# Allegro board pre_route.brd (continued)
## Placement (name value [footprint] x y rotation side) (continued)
CN2  0.1uf  [8_PINS_SURFACE_MOUNT]  -155.7 262.49 0 top
CN3  0.1uf  [8_PINS_SURFACE_MOUNT]  -155.7 266.78 0 top
CN4  0.1uf  [8_PINS_SURFACE_MOUNT]  -155.7 271.07 0 top
CN5  0.1uf  [8_PINS_SURFACE_MOUNT]  -155.7 275.36 0 top
CN6  0.1uf  [8_PINS_SURFACE_MOUNT]  -155.7 279.65 0 top
CN7  0.1uf  [8_PINS_SURFACE_MOUNT]  -155.7 236.76 0 top
CN8  0.1uf  [8_PINS_SURFACE_MOUNT]  -155.7 283.94 0 top
CN9  0.1uf  [8_PINS_SURFACE_MOUNT]  -155.7 232.47 0 top
CN10  0.1uf  [8_PINS_SURFACE_MOUNT]  -155.7 245.33 0 top
CN11  0.1uf  [8_PINS_SURFACE_MOUNT]  -155.7 249.62 0 top
CN12  0.1uf  [8_PINS_SURFACE_MOUNT]  -155.7 253.91 0 top
CN13  0.1uf  [8_PINS_SURFACE_MOUNT]  -155.7 258.2 0 top
CON3  VAL  [CFCONN50P]  -25.15 297.56 0 top
HS1  XXX  [HEATSINK-7106D]  162.5 257.94 0 bottom
HS2  XXX  [HEATSINK-7106D]  249.87 36.45 0 bottom
ISO1  XXX  [DIP8]  22.23 202.56 0 top
J1  XXX  [CON120_HM-ZD]  175.26 303.27 180 top
J2  XXX  [VERT_SM_SMA]  237.49 295.91 0 top
J3  XXX  [VERT_SM_SMA]  250.19 295.91 0 top
J4  XXX  [VERT_SM_SMA]  262.89 295.91 0 top
J5  XXX  [VERT_SM_SMA]  275.59 295.91 0 top
J6  XXX  [VERT_SM_SMA]  288.29 295.91 0 top
J11  XXX  [HSSDC2]  326.06 281.3 0 top
J15  XXX  [HSSDC2]  326.06 264.16 0 top
J16  XXX  [VERT_SM_SMA]  219.71 257.81 0 top
J17  XXX  [VERT_SM_SMA]  250.19 255.27 0 top
J18  XXX  [VERT_SM_SMA]  262.89 255.27 0 top
J19  XXX  [VERT_SM_SMA]  275.59 255.27 0 top
J20  XXX  [VERT_SM_SMA]  288.29 255.27 0 top
J23  XXX  [HSSDC2]  326.06 247.01 0 top
J24  XXX  [VERT_SM_SMA]  219.71 245.11 0 top
J25  XXX  [VERT_SM_SMA]  250.19 242.57 0 top
J26  XXX  [VERT_SM_SMA]  262.89 242.57 0 top
J27  XXX  [VERT_SM_SMA]  275.59 242.57 0 top
J28  XXX  [VERT_SM_SMA]  288.29 242.57 0 top
J29  XXX  [VERT_SM_SMA]  154.94 236.22 270 top
J30  XXX  [VERT_SM_SMA]  167.64 236.22 0 top
J31  XXX  [MOLEX-10X2]  28.83 249.43 90 top
J32  XXX  [HSSDC2]  326.06 229.87 0 top
J34  XXX  [MICTOR]  279.4 226.06 0 top
J36  VAL  [HDR2X4_100MIL]  230.25 276.23 270 top
J37  XXX  [VERT_SM_SMA]  152.4 191.77 270 top
J38  XXX  [SFP]  298.98 204.26 90 top
J42  XXX  [TEK_PROBE]  210.19 196.85 90 top
J43  XXX  [VERT_SM_SMA]  152.4 179.07 0 top
J45  XXX  [SFP]  298.98 183.94 90 top
J46  XXX  [VERT_SM_SMA]  110.49 176.53 90 top
J47  XXX  [VERT_SM_SMA]  124.46 176.53 90 top
J48  XXX  [TH-CONN-2-P1]  19.69 186.69 270 top
J49  XXX  [VERT_SM_SMA]  165.1 182.88 270 top
J52  XXX  [VERT_SM_SMA]  252.73 173.35 90 top
J53  XXX  [TSM-110-01-G-DV]  266.7 170.18 0 top
J54  XXX  [SFP]  298.98 163.62 90 top
J55  XXX  [TH-CONN-2-P1]  132.72 165.1 0 top
J56  XXX  [TH-CONN-2-P1]  150.5 165.1 180 top
J57  XXX  [SMT_A_PROBE]  225.42 161.93 270 top
J58  XXX  [SMT_A_PROBE]  236.85 161.93 270 top
J59  XXX  [TEK_PROBE]  210.19 161.92 90 top
J60  XXX  [VERT_SM_SMA]  252.73 160.66 90 top
J61  XXX  [VERT_SM_SMA]  127.63 158.11 90 top
J62  XXX  [VERT_SM_SMA]  142.24 158.11 90 top
J63  XXX  [TSM-105-01-L-DV]  266.7 147.32 0 top
J64  XXX  [SFP]  298.98 143.3 90 top
J68  XXX  [TSM-110-01-G-DV]  170.81 146.05 180 top
J69  XXX  [VERT_SM_SMA]  210.82 138.43 0 top
J72  XXX  [EDGE_LAUNCHED_SMA]  329.39 128.31 0 top
J75  XXX  [MICTOR]  102.23 146.05 180 top
J76  XXX  [VERT_SM_SMA]  207.64 117.47 0 top
J77  XXX  [EDGE_LAUNCHED_SMA]  329.39 113.07 0 top
J78  XXX  [HDR2X10_100MIL]  39.37 106.68 270 top
J79  XXX  [HDR2X7_100MIL]  68.58 106.68 270 top
J80  XXX  [VERT_SM_SMA]  196.22 102.87 270 top
J81  XXX  [EDGE_LAUNCHED_SMA]  329.39 97.83 0 top
J83  XXX  [VERT_SM_SMA]  279.4 93.98 0 top
J84  XXX  [VERT_SM_SMA]  299.72 93.98 0 top
J85  XXX  [TSM-105-01-L-DV]  96.52 91.44 270 top
J86  XXX  [EDGE_LAUNCHED_SMA]  329.39 82.59 0 top
J87  XXX  [10_PIN_CONNECTOR]  96.52 80.64 270 top
J88  XXX  [VERT_SM_SMA]  279.4 78.74 0 top
J89  XXX  [VERT_SM_SMA]  299.72 78.74 0 top
J90  XXX  [TH-CONN-2-P1]  132.08 75.56 90 top
J91  XXX  [VERT_SM_SMA]  177.8 74.93 270 top
J92  XXX  [HDR2X20_100MIL]  52.07 73.66 270 top
J93  XXX  [EDGE_LAUNCHED_SMA]  329.39 67.32 0 top
J94  XXX  [VERT_SM_SMA]  279.4 63.5 0 top
J95  XXX  [VERT_SM_SMA]  299.72 63.5 0 top
J97  XXX  [VERT_SM_SMA]  196.85 54.61 90 top
J98  XXX  [EDGE_LAUNCHED_SMA]  329.39 52.08 0 top
J99  XXX  [VERT_SM_SMA]  279.4 48.26 0 top
J100  XXX  [VERT_SM_SMA]  299.72 48.26 0 top
J101  XXX  [EDGE_LAUNCHED_SMA]  329.39 36.73 0 top
J102  XXX  [VERT_SM_SMA]  279.4 33.02 0 top
J103  XXX  [VERT_SM_SMA]  299.72 33.02 0 top
J104  XXX  [VERT_SM_SMA]  177.8 31.75 90 top
J105  XXX  [EDGE_LAUNCHED_SMA]  329.39 21.49 0 top
J106  XXX  [VERT_SM_SMA]  279.4 17.78 0 top
J107  XXX  [VERT_SM_SMA]  299.72 17.78 0 top
J108  XXX  [CON120_HM-ZD]  167.46 1.91 0 top
J109  XXX  [CON120_HM-ZD]  204.47 1.91 0 top
J111  XXX  [TH-CONN-2-P1]  28.32 257.68 180 top
J112  XXX  [TH-CONN-2-P1]  154.43 267.08 0 top
J113  XXX  [TH-CONN-2-P1]  156.21 204.72 270 top
J114  XXX  [TH-CONN-2-P1]  136.14 278.38 0 top
J121  XXX  [VERT_SM_SMA]  313.69 295.91 0 top
J122  XXX  [VERT_SM_SMA]  300.99 295.91 0 top
J123  VAL  [HDR2X2_100MIL]  230.25 285.75 270 top
J124  XXX  [DB9DOUBLE]  16.51 49.53 90 top
NOREF  -  []  165.73 167.64 0 top
NOREF#2  -  []  75.34 280.47 0 top
NOREF#3  -  []  5.84 280.47 0 top
NOREF#4  -  [unnamed#2]  162.56 161.29 0 top
NOREF#5  -  [unnamed#2]  165.73 173.99 0 top
NOREF#6  -  []  323.85 6.35 0 top
NOREF#7  -  []  6.35 298.45 0 top
NOREF#8  -  [unnamed#2]  326.39 292.1 0 top
NOREF#9  -  [unnamed#2]  111.76 110.49 0 top
NOREF#10  -  []  6.35 6.35 0 top
NOREF#11  -  [unnamed#2]  229.23 301.62 0 top
NOREF#12  -  [unnamed#2]  25.4 7.62 0 top
NOREF#13  -  [unnamed#2]  210.82 17.78 0 top
NOREF#14  -  []  165.73 167.64 0 top
NOREF#15  -  [unnamed#2]  63.5 116.84 0 top
NOREF#16  -  [unnamed#2]  313.69 13.97 0 top
NOREF#17  -  [unnamed#2]  219.71 226.06 0 top
NOREF#18  -  []  -39.38 -132.66 0 top
NOREF#19  -  []  0.63 304.8 0 top
NOREF#20  -  []  -316.23 56.52 0 top
NOREF#21  -  [unnamed#2]  6.35 289.56 0 top
NOREF#22  -  []  323.85 6.35 0 top
NOREF#23  -  [unnamed#2]  222.25 127 0 top
NOREF#24  -  [unnamed#2]  275.59 199.39 0 top
NOREF#25  -  [unnamed#2]  101.6 10.79 0 top
NOREF#26  -  []  6.35 6.35 0 top
NOREF#27  -  [unnamed#2]  245.11 6.22 0 top
NOREF#28  -  []  330.2 0 0 top
NOREF#29  -  []  0 0 0 top
NOREF#30  -  [unnamed#2]  210.82 17.78 180 bottom
NOREF#31  -  [unnamed#2]  63.5 116.84 180 bottom
NOREF#32  -  [unnamed#2]  25.4 7.62 180 bottom
NOREF#33  -  [unnamed#2]  245.11 6.22 180 bottom
NOREF#34  -  [unnamed#2]  165.73 173.99 180 bottom
NOREF#35  -  [unnamed#2]  326.39 292.1 180 bottom
NOREF#36  -  [unnamed#2]  229.23 301.62 180 bottom
NOREF#37  -  [unnamed#2]  313.69 13.97 180 bottom
NOREF#38  -  [unnamed#2]  101.6 10.79 180 bottom
NOREF#39  -  [unnamed#2]  6.35 289.56 180 bottom
PMCJN1  XXX  [SMT]  22.09 164.46 0 bottom
PMCJN2  XXX  [SMT]  22.09 150.46 0 bottom
R1  56  [RES_0402]  -111.7 60.39 0 top
R2  0.056  [THRU_HOLE]  -141.15 49.7 0 top
R3  100  [RES_0402]  -137.2 32.51 0 top
R4  104  [RES_0603]  -144.92 150.21 0 top
R5  20  [RES_0603]  -144.92 146.55 0 top
R6  100  [RES_0402]  -137.2 16.51 0 top
R7  56  [RES_0603]  -111.67 96.71 0 top
R11  56  [RES_0603]  -111.67 136.92 0 top
R15  104  [RES_0402]  -139.05 274.73 0 top
R16  78.7  [RES_0402]  -139.05 256.44 0 top
R17  6.65K  [RES_0402]  -139.05 129.85 0 top
R18  100  [RES_0402]  -137.2 55.37 0 top
R19  4.42K  [RES_0402]  -139.05 70.45 0 top
R21  0  [RES_0402]  -139.05 43.58 0 top
R23  56  [RES_0603]  -111.67 107.68 0 top
R27  162  [RES_0402]  -144.74 263.32 0 top
R28  1.0K  [RES_0402]  -139.05 27.12 0 top
R30  56  [RES_0603]  -111.67 104.02 0 top
R31  1.0K  [RES_0402]  -139.05 24.84 0 top
R32  1.0K  [RES_0402]  -139.05 22.55 0 top
R33  100  [RES_0402]  -137.2 30.22 0 top
R34  2.7K  [RES_0402]  -144.74 171.91 0 top
R35  162  [RES_0402]  -144.74 261.03 0 top
R37  10.0K  [RES_0603]  -137.38 160.27 0 top
R39  1.0K  [RES_0603]  -137.38 284.57 0 top
R40  162  [RES_0402]  -144.74 258.74 0 top
R41  1.0K  [RES_0603]  -137.38 280.91 0 top
R42  10.0K  [RES_0603]  -137.38 156.61 0 top
R43  100  [RES_0402]  -137.2 18.79 0 top
R44  1.0K  [RES_0603]  -137.38 277.25 0 top
R46  162  [RES_0402]  -144.74 256.46 0 top
R47  162  [RES_0402]  -144.74 254.17 0 top
R48  162  [RES_0402]  -144.74 251.89 0 top
R51  10.0K  [RES_0603]  -137.38 152.96 0 top
R52  22  [RES_0402]  -137.2 129.87 0 top
R53  1.0K  [RES_0603]  -137.38 273.6 0 top
R55  10.0K  [RES_0603]  -137.38 149.3 0 top
R56  1.0K  [RES_0603]  -137.38 269.94 0 top
R57  1.0K  [RES_0603]  -137.38 266.29 0 top
R60  100  [RES_0402]  -137.2 14.22 0 top
R61  100  [RES_0402]  -137.2 11.94 0 top
R62  4.7  [RES_0603]  -139.23 60.16 0 top
R65  2.5K  [RES_0603]  -144.92 69.78 0 top
R66  2.5K  [RES_0603]  -144.92 73.44 0 top
R67  2.5K  [RES_0603]  -144.92 77.09 0 top
R68  1.0K  [RES_0603]  -137.38 262.63 0 top
R70  56  [RES_0603]  -111.67 93.05 0 top
R71  4.7  [RES_0603]  -139.23 56.51 0 top
R73  56  [RES_0603]  -111.67 85.74 0 top
R74  1.0K  [RES_0402]  -139.05 20.27 0 top
R75  1.0K  [RES_0402]  -139.05 17.98 0 top
R76  10.0K  [RES_0603]  -144.92 142.9 0 top
R77  10.0K  [RES_0603]  -144.92 139.24 0 top
R80  2.5K  [RES_0603]  -144.92 80.75 0 top
R81  2.5K  [RES_0603]  -144.92 84.4 0 top
R82  2.5K  [RES_0603]  -144.92 88.06 0 top
R83  2.5K  [RES_0603]  -144.92 91.71 0 top
R84  2.5K  [RES_0603]  -144.92 95.37 0 top
R85  2.5K  [RES_0603]  -144.92 99.03 0 top
R86  100  [RES_0402]  -139.05 183.31 0 top
R87  104  [RES_0402]  -139.05 265.58 0 top
R88  78.7  [RES_0402]  -139.05 247.3 0 top
R89  78.7  [RES_0402]  -139.05 245.01 0 top
R90  104  [RES_0402]  -139.05 263.3 0 top
R91  104  [RES_0402]  -139.05 261.01 0 top
R92  78.7  [RES_0402]  -139.05 242.72 0 top
R93  78.7  [RES_0402]  -139.05 240.44 0 top
R94  104  [RES_0402]  -139.05 258.73 0 top
R98  10.0K  [RES_0603]  6.35 144.14 0 top
R99  2.5K  [RES_0603]  -144.92 102.68 0 top
R100  2.5K  [RES_0603]  -144.92 66.12 0 top
R101  2.0K  [RES_0603]  -144.92 106.34 0 top
R102  11.0K  [RES_0603]  -144.92 128.27 0 top
R103  24.9  [RES_0603]  -111.67 184.45 0 top
R104  24.9  [RES_0603]  -111.67 180.79 0 top
R105  60.0K  [RES_0603]  -111.67 162.51 0 top
R106  60.0K  [RES_0603]  -111.67 169.83 0 top
R107  60.0K  [RES_0603]  -111.67 166.17 0 top
R108  60.0K  [RES_0603]  -111.67 151.55 0 top
R109  60.0K  [RES_0603]  -111.67 158.86 0 top
R110  60.0K  [RES_0603]  -111.67 155.2 0 top
R111  60.0K  [RES_0603]  -111.67 129.61 0 top
R112  60.0K  [RES_0603]  -111.67 147.89 0 top
R113  60.0K  [RES_0603]  -111.67 144.24 0 top
R114  60.0K  [RES_0603]  -111.67 140.58 0 top
R115  499  [RES_0603]  -111.67 78.43 0 top
R116  24.9  [RES_0603]  -111.67 173.48 0 top
R117  22K  [RES_0603]  -111.67 74.77 0 top
R118  24.9  [RES_0603]  -111.67 177.14 0 top
R119  1.0K  [RES_0603]  -111.67 71.12 0 top
R120  1.0K  [RES_0603]  -111.67 67.46 0 top
R121  11.0K  [RES_0603]  -144.92 131.93 0 top
R122  30K  [RES_0603]  -137.38 258.98 0 top
R123  10.0K  [RES_0603]  -137.38 255.32 0 top
R124  200  [RES_0603]  -137.38 8.97 0 top
R125  11.0K  [RES_0603]  -144.92 135.58 0 top
R126  NI  [RES_0402]  -137.2 139.02 0 top
R127  22  [RES_0402]  -137.2 132.16 0 top
R128  11.0K  [RES_0603]  -111.67 188.1 0 top
R129  23  [RES_0603]  -137.38 126.9 0 top
R130  1.0K  [RES_0603]  -111.67 63.81 0 top
R131  250  [RES_0603]  -137.38 123.25 0 top
R132  250  [RES_0603]  -137.38 119.59 0 top
R133  10.0K  [RES_0603]  -137.38 251.66 0 top
R134  47  [RES_0603]  -137.38 94 0 top
R135  100  [RES_0402]  -137.2 87.37 0 top
R136  56  [RES_0402]  -137.2 5.99 0 top
R137  100  [RES_0402]  -137.2 85.09 0 top
R138  100  [RES_0402]  -137.2 82.8 0 top
R139  49.9  [RES_0603]  -137.38 3.02 0 top
R140  1.0K  [RES_0603]  -111.67 19.94 0 top
R141  49.9  [RES_0603]  -139.23 302.85 0 top
R142  10.0K  [RES_0603]  -137.38 248.01 0 top
R143  10.0K  [RES_0603]  -137.38 244.35 0 top
R144  10.0K  [RES_0603]  -137.38 240.7 0 top
R145  10.0K  [RES_0603]  -137.38 237.04 0 top
R146  10.0K  [RES_0603]  -137.38 233.38 0 top
R147  10.0K  [RES_0603]  -137.38 145.64 0 top
R148  10.0K  [RES_0603]  -137.38 226.07 0 top
R149  NI  [RES_0402]  -139.05 299.87 0 top
R150  100  [RES_0402]  -137.2 80.52 0 top
R151  100  [RES_0402]  -137.2 78.23 0 top
R152  100  [RES_0402]  -137.2 75.94 0 top
R153  100  [RES_0402]  -137.2 73.66 0 top
R154  100  [RES_0402]  -137.2 71.37 0 top
R155  100  [RES_0402]  -137.2 69.09 0 top
R156  100  [RES_0402]  -137.2 66.8 0 top
R157  100  [RES_0402]  -137.2 64.51 0 top
R158  10.0K  [RES_0603]  -137.38 222.42 0 top
R159  1.0K  [RES_0603]  -111.67 56.5 0 top
R160  1.0K  [RES_0603]  -111.67 52.84 0 top
R161  4.7K  [RES_0603]  -139.23 237.47 0 top
R162  4.7K  [RES_0603]  -139.23 233.81 0 top
R163  1.0K  [RES_0603]  -139.23 143.79 0 top
R164  1.0K  [RES_0603]  -139.23 140.13 0 top
R165  100  [RES_0402]  -137.2 62.23 0 top
R167  100  [RES_0402]  -137.2 59.94 0 top
R168  100  [RES_0402]  -137.2 57.66 0 top
R169  1.0K  [RES_0603]  -139.23 136.47 0 top
R170  1.0K  [RES_0603]  -139.23 132.82 0 top
R171  NI  [RES_0402]  -139.05 297.59 0 top
R172  1.0K  [RES_0603]  -111.67 49.18 0 top
R173  4.7K  [RES_0603]  -139.23 230.16 0 top
R174  4.7K  [RES_0603]  -139.23 226.5 0 top
R175  20.0K  [RES_0603]  -139.23 126.88 0 top
R176  49.9  [RES_0402]  -139.05 123.91 0 top
R177  49.9  [RES_0402]  -139.05 121.62 0 top
R178  0  [RES_0603]  -139.23 111.34 0 top
R179  0  [RES_0603]  -139.23 107.68 0 top
R180  NI  [RES_0402]  -139.05 295.3 0 top
R181  NI  [RES_0402]  -139.05 293.02 0 top
R182  NI  [RES_0402]  -139.05 290.73 0 top
R183  NI  [RES_0402]  -139.05 288.44 0 top
R184  NI  [RES_0402]  -139.05 286.16 0 top
R185  200  [RES_0805]  -139.55 81.86 0 top
R186  NI  [RES_0402]  -139.05 283.87 0 top
R187  226  [RES_0805]  -139.55 77.75 0 top
R189  10k  [RES_0805]  -139.55 73.64 0 top
R190  4.7  [RES_0603]  -139.23 67.47 0 top
R191  78.7  [RES_0402]  -139.05 254.15 0 top
R192  104  [RES_0402]  -139.05 272.44 0 top
R193  104  [RES_0402]  -139.05 270.16 0 top
R194  78.7  [RES_0402]  -139.05 251.87 0 top
R195  104  [RES_0402]  -139.05 267.87 0 top
R196  78.7  [RES_0402]  -139.05 249.58 0 top
R202  4.7  [RES_0603]  -139.23 63.82 0 top
R203  NI  [RES_0402]  -139.05 281.59 0 top
R204  200  [RES_0603]  -137.38 141.99 0 top
R205  4.7K  [RES_0603]  -139.23 222.84 0 top
R206  4.7K  [RES_0603]  -139.23 219.19 0 top
R207  1.0K  [RES_0603]  -111.67 45.53 0 top
R208  NI  [RES_0402]  -139.05 279.3 0 top
R209  4.7K  [RES_0603]  -139.23 215.53 0 top
R210  4.7K  [RES_0603]  -139.23 211.88 0 top
R211  4.7K  [RES_0603]  -139.23 208.22 0 top
R212  NI  [RES_0402]  -139.05 277.01 0 top
R214  100  [RES_0402]  -137.2 53.08 0 top
R215  10k  [RES_0402]  -139.05 39.01 0 top
R216  10.0K  [RES_0603]  -137.38 218.76 0 top
R217  4.7K  [RES_0603]  -139.23 204.56 0 top
R218  4.7K  [RES_0603]  -139.23 200.91 0 top
R219  4.7K  [RES_0603]  -139.23 197.25 0 top
R220  4.7K  [RES_0603]  -139.23 193.6 0 top
R221  4.7K  [RES_0603]  -139.23 189.94 0 top
R222  93  [RES_0603]  -139.23 36.04 0 top
R223  158  [RES_0603]  -139.23 32.38 0 top
R224  4.7K  [RES_0603]  -139.23 186.29 0 top
R225  1.0K  [RES_0402]  -139.05 29.41 0 top
R226  4.7K  [RES_0603]  -147.41 295.53 0 top
R227  4.7K  [RES_0603]  -139.23 180.34 0 top
R228  4.7K  [RES_0603]  -139.23 176.69 0 top
R229  4.7K  [RES_0603]  -139.23 173.03 0 top
R230  4.7K  [RES_0603]  -139.23 169.38 0 top
R231  10.0K  [RES_0603]  -137.38 215.11 0 top
R232  10.0K  [RES_0603]  -137.38 211.45 0 top
R233  10.0K  [RES_0603]  -137.38 207.79 0 top
R235  4.7K  [RES_0603]  -139.23 165.72 0 top
R236  56  [RES_0603]  -111.67 122.3 0 top
R237  4.7K  [RES_0603]  -139.23 162.06 0 top
R238  56  [RES_0603]  -111.67 118.64 0 top
R239  4.7K  [RES_0603]  -139.23 158.41 0 top
R241  4.7K  [RES_0603]  -139.23 154.75 0 top
R242  250  [RES_0603]  -139.23 15.01 0 top
R243  49.9  [RES_0402]  -139.05 12.04 0 top
R244  49.9  [RES_0402]  -139.05 9.75 0 top
R247  1.0K  [RES_0603]  -137.38 90.34 0 top
R248  787  [RES_0603]  -144.92 3.97 0 top
R249  15.0K  [RES_0603]  -139.23 6.78 0 top
R250  15.0K  [RES_0603]  -139.23 3.13 0 top
R251  15.0K  [RES_0603]  -144.92 302.85 0 top
R252  15.0K  [RES_0603]  -144.92 299.19 0 top
R253  15.0K  [RES_0603]  -144.92 295.53 0 top
R254  15.0K  [RES_0603]  -144.92 291.88 0 top
R255  15.0K  [RES_0603]  -144.92 288.22 0 top
R256  15.0K  [RES_0603]  -144.92 284.57 0 top
R257  15.0K  [RES_0603]  -144.92 280.91 0 top
R258  15.0K  [RES_0603]  -144.92 277.25 0 top
R259  0  [RES_0603]  -144.92 273.6 0 top
R260  1.0K  [RES_0603]  -111.67 41.87 0 top
R261  47  [RES_0603]  -144.92 269.94 0 top
R262  1.0K  [RES_0603]  -111.67 38.22 0 top
R263  1.0K  [RES_0603]  -111.67 34.56 0 top
R264  1.0K  [RES_0603]  -111.67 30.9 0 top
R265  1.0K  [RES_0603]  -111.67 27.25 0 top
R266  1.0K  [RES_0603]  -111.67 23.59 0 top
R267  1.0K  [RES_0603]  -137.38 229.73 0 top
R268  1.0K  [RES_0603]  -111.67 16.28 0 top
R269  1.0K  [RES_0603]  -111.67 12.63 0 top
R270  100  [RES_0402]  -137.2 50.8 0 top
R271  100  [RES_0402]  -137.2 48.51 0 top
R272  100  [RES_0402]  -137.2 46.23 0 top
R273  100  [RES_0402]  -137.2 43.94 0 top
R274  100  [RES_0402]  -137.2 41.65 0 top
R275  100  [RES_0402]  -137.2 39.37 0 top
R276  100  [RES_0402]  -137.2 37.08 0 top
R277  100  [RES_0402]  -137.2 34.8 0 top
R278  1.0K  [RES_0603]  -111.67 8.97 0 top
R279  10.0K  [RES_0603]  -137.38 204.14 0 top
R280  10.0K  [RES_0603]  -137.38 200.48 0 top
R281  10.0K  [RES_0603]  -137.38 196.83 0 top
R282  1.0K  [RES_0603]  -111.67 5.31 0 top
R283  1.0K  [RES_0603]  -111.67 1.66 0 top
R284  1.0K  [RES_0603]  -137.38 302.85 0 top
R285  1.0K  [RES_0603]  -137.38 299.19 0 top
R286  1.0K  [RES_0603]  -137.38 295.53 0 top
R289  10.0K  [RES_0603]  -137.38 193.17 0 top
R290  10.0K  [RES_0603]  -137.38 189.51 0 top
R291  10.0K  [RES_0603]  -137.38 185.86 0 top
R292  10.0K  [RES_0603]  -137.38 182.2 0 top
R293  10.0K  [RES_0603]  -137.38 178.55 0 top
R294  10.0K  [RES_0603]  -137.38 174.89 0 top
R296  1.0K  [RES_0603]  -137.38 291.88 0 top
R297  78.7  [RES_0603]  -144.92 248.92 0 top
R298  47  [RES_0603]  -144.92 266.29 0 top
R299  1.0K  [RES_0603]  -137.38 288.22 0 top
R300  47  [RES_0603]  -144.92 245.26 0 top
R301  47  [RES_0603]  -144.92 241.6 0 top
R303  1.0K  [RES_0603]  -144.92 237.95 0 top
R304  10.0K  [RES_0603]  -144.92 230.64 0 top
R305  1.0K  [RES_0603]  -144.92 234.29 0 top
R306  5.6K  [RES_0603]  -144.92 219.67 0 top
R307  5.6K  [RES_0603]  -144.92 216.01 0 top
R318  10.0K  [RES_0603]  -144.92 226.98 0 top
R319  10.0K  [RES_0603]  -144.92 223.32 0 top
R322  100  [RES_0402]  -144.74 209.39 0 top
R323  100  [RES_0402]  -144.74 207.1 0 top
R324  0  [RES_0603]  -139.23 104.03 0 top
R326  0  [RES_0603]  -139.23 100.37 0 top
R327  0  [RES_0603]  -139.23 114.99 0 top
R329  NI  [RES_0603]  -144.92 204.13 0 top
R330  NI  [RES_0603]  -144.92 200.47 0 top
R331  NI  [RES_0603]  -144.92 196.82 0 top
R332  NI  [RES_0603]  -144.92 193.16 0 top
R333  NI  [RES_0603]  -144.92 189.51 0 top
R334  0  [RES_0603]  -139.23 96.71 0 top
R335  0  [RES_0603]  -139.23 93.06 0 top
R336  0  [RES_0603]  -139.23 89.4 0 top
R337  0  [RES_0603]  -139.23 85.75 0 top
R338  NI  [RES_0603]  -144.92 185.85 0 top
R339  NI  [RES_0603]  -144.92 182.19 0 top
R340  NI  [RES_0603]  -144.92 178.54 0 top
R341  NI  [RES_0603]  -144.92 174.88 0 top
R342  100  [RES_0402]  -137.2 27.94 0 top
R343  100  [RES_0402]  -137.2 25.65 0 top
R344  0  [RES_0402]  -139.05 41.29 0 top
R345  NI  [RES_0402]  -137.2 136.73 0 top
R346  100  [RES_0402]  -137.2 23.37 0 top
R347  100  [RES_0402]  -137.2 21.08 0 top
R348  0  [RES_0603]  -144.92 168.94 0 top
R349  0  [RES_0603]  -144.92 165.28 0 top
R350  NI  [RES_0603]  -144.92 161.63 0 top
R351  NI  [RES_0603]  -144.92 157.97 0 top
R352  750K  [RES_0805]  -145.24 154.09 0 top
R353  5.6K  [RES_0603]  -144.92 212.36 0 top
R354  3.0K  [RES_0603]  -147.41 299.19 0 top
R355  NI  [RES_0402]  -137.2 134.45 0 top
R357  6.2K  [RES_0603]  -147.41 302.85 0 top
R358  10.0K  [RES_0603]  -137.38 171.24 0 top
R359  10.0K  [RES_0603]  -137.38 167.58 0 top
R360  10.0K  [RES_0603]  -137.38 163.92 0 top
R361  0  [RES_0603]  -139.23 118.65 0 top
RJ1  XXX  [RJ426]  -119.16 202.11 0 top
RN5  56  [16_PIN_SMD]  -112.58 192.43 0 top
RN14  1.0K  [RPACK8]  -112.58 282.18 0 top
RN15  10K  [RN_SMT]  -112.58 302.17 0 top
RN16  10K  [RN_SMT]  -103.44 6.3 0 top
RN17  10K  [RN_SMT]  -103.44 11.3 0 top
RN18  10K  [RN_SMT]  -103.44 16.3 0 top
RN19  10.0K  [RN_SMT]  -103.44 21.3 0 top
RN20  10.0K  [RN_SMT]  -103.44 26.3 0 top
RN21  220  [RN_SMT]  -103.44 31.3 0 top
RN22  220  [RN_SMT]  -103.44 36.29 0 top
RN23  56  [16_PIN_SMD]  -103.44 61.29 0 top
RN24  56  [16_PIN_SMD]  -103.44 66.29 0 top
RN25  56  [16_PIN_SMD]  -103.44 71.28 0 top
RN26  56  [16_PIN_SMD]  -103.44 76.28 0 top
RN27  56  [16_PIN_SMD]  -103.44 81.28 0 top
RN28  56  [16_PIN_SMD]  -103.44 86.28 0 top
RN29  56  [16_PIN_SMD]  -103.44 91.28 0 top
RN30  56  [16_PIN_SMD]  -103.44 96.28 0 top
RN31  56  [16_PIN_SMD]  -103.44 101.28 0 top
RN32  56  [16_PIN_SMD]  -103.44 106.27 0 top
RN33  220  [RN_SMT]  -103.44 41.29 0 top
RN34  220  [RN_SMT]  -103.44 46.29 0 top
RN35  220  [RN_SMT]  -103.44 51.29 0 top
RN36  220  [RN_SMT]  -103.44 56.29 0 top
RN37  1.0K  [RPACK8]  -112.58 287.18 0 top
RN38  1.0K  [RPACK8]  -112.58 292.18 0 top
RN39  1.0K  [RPACK8]  -112.58 297.18 0 top
U1  XXX  [TO263_5]  162.5 258.57 270 bottom
U2  XXX  [TO263]  249.87 36.45 0 bottom
U4  XXX  [TSSOP_8]  165.73 217.17 270 top
U5  XXX  [QSOP16]  266.7 209.55 270 top
U6  XXX  [TSSOP20]  165.1 205.1 270 top
U7  XXX  [F1020]  233.81 208.66 90 top
U8  XXX  [BRICK7]  98.68 186.82 180 top
U9  VAL  [TSSOP8]  164.47 192.41 270 top
U10  XXX  [LQFP_32]  139.05 173.99 90 top
U11  XXX  [TQFP128P]  45.72 137.79 0 top
U12  XXX  [QSOP16]  114.93 133.35 180 top
U13  XXX  [SOIC8]  203.2 131.44 90 top
U14  XXX  [SOG_05]  284.86 123.95 0 bottom
U15  XXX  [F1020]  145.41 128.91 90 top
U17  XXX  [SOG_65]  293.12 123.44 270 bottom
U18  XXX  [TSSOP20]  181.61 98.42 90 top
U19  XXX  [SO40]  118.74 93.34 270 top
U20  XXX  [SO40]  132.72 93.34 90 top
U21  XXX  [SO40]  148.59 93.34 90 top
U22  XXX  [SO24]  32.38 89.53 270 top
U23  XXX  [SO24]  50.8 89.53 270 top
U24  XXX  [SO24]  68.58 89.53 270 top
U25  XXX  [TSSOP48]  145.41 76.2 90 top
U26  XXX  [TSSOP48]  163.19 76.2 90 top
U27  XXX  [XPAK1]  247.65 123.82 0 top
U28  XXX  [SOG_50]  25.4 60.96 180 top
U29  XXX  [PQFP100_720X956]  95.25 55.88 0 top
U30  XXX  [PQFP100_720X956]  123.19 55.88 0 top
U31  XXX  [TSOP48]  56.52 55.25 180 top
U32  XXX  [TSSOP20]  181.61 55.25 90 top
U33  XXX  [SOG_50]  25.4 46.99 180 top
U34  XXX  [TSSOP48]  69.85 32.38 90 top
U36  XXX  [SOIC20]  146.69 203.45 270 top
U37  XXX  [SOIC20]  137.41 268.86 0 top
U38  VAL  [SO8]  144.91 280.67 90 top
U39  XXX  [SO24]  68.58 104.77 90 bottom
U42  XXX  [TO263_5]  55.8 262.18 0 top
U43  VAL  [SOIC16F]  38.1 60.96 180 top
U44  VAL  [SOIC16F]  38.1 46.99 180 top
U45  XXX  [BRICK_8]  98.68 219.2 180 top
U46  XXX  [SOIC8]  196.88 61.93 0 top
U47  XXX  [SOIC8]  198.5 110.24 0 top
U52  XXX  [SO24]  50.8 104.77 90 bottom
U53  -  [SO8N]  157.48 274.32 270 top
U59  VAL  [SSOT6]  14.72 95.45 270 top
U60  VAL  [SOT23-5]  172.09 199.64 90 bottom
XU2  -  [DIMM240]  191.9 208.66 90 top
Y1  XXX  [4P_OSC]  210.19 129.54 270 top
Y2  XXX  [4P_OSC]  179.7 86.36 90 top
Y3  XXX  [4P_OSC]  179.7 43.18 90 top
Y4  XXX  [PACKAGE_D]  34.29 120.02 180 top

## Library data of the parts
C1-C8 C10 C11 C17 C18 C20-C25 C29-C32 C83 C101 C104 C105 C115 C518 C526 C532 C667 C668 C673 C725 C752 C753 = CAP_SMD_NPOL_0: Tolerance: XXX; User Part Number: ECJ-0EB1C103K; part number: CAP_SMD_NPOL_0-0.01UF,5%,CAP_0402
C9 C14 C15 = CAP_SMD_NPOL_0: User Part Number: ECJ-3YF1A106Z; Tolerance: XXX; part number: CAP_SMD_NPOL_0-10UF,5%,CAP_1206
C12 C50-C53 C60 C72 C77 C80 C678 C679 C686-C690 C693 C695 = CAP_SMD_POL_0: User Part Number: ECS-T1AX106R; Tolerance: TOL; part number: CAP_SMD_POL_0-10UF,5%,10V,CAPT_3528
C13 C16 C44 C45 C54 C55 C84 C87 C89 C90 C92 C102 C110-C114 C116-C120 C122 C134 C135 C141 C143 C147 C148 C165 C169 C171 C172 C174 C176 C178 C180 C182 C183 C186 C188 C196-C198 C205 C214 C218 C220 C226 C228 C230 C237-C240 C247 C249 C256 C257 C261 C273 C274 C276 C277 C279 C280 C282-C284 C287 C288 C290 C294-C298 C301 C302 C310-C312 C315 C319 C323 C325-C327 C331 C336 C338 C340 C342 C345 C347 C348 C350-C352 C354 C357 C358 C360 C363 C369-C372 C374 C377 C378 C380 C385 C387 C388 C390 C394 C401 C403 C408 C409 C414 C415 C421 C424 C426 C429 C430 C433 C439 C447 C451 C452 C458 C464 C466 C467 C469 C470 C472 C475 C477 C480-C482 C484 C485 C488 C493 C495-C502 C505 C513 C517 C520-C522 C525 C531 C536-C538 C540 C543 C544 C546 C550 C551 C553 C555 C557 C562 C566 C568 C571 C572 C578 C579 C581 C583 C584 C588 C590 C591 C593 C596 C599 C601 C602 C604 C605 C608 C610 C613 C615 C620 C626 C636 C640 C642-C648 C651-C657 C659-C666 C669 C670 C672 C674 C684 C685 C691 C692 C694 C702 C703 C706 C715 C718-C722 C726 C733 C735 C745-C751 = CAP_SMD_NPOL_0: Tolerance: XXX; User Part Number: ECJ-1VB1C104K; part number: CAP_SMD_NPOL_0-0.1UF,5%,CAP_0603
C19 C210 C698-C701 C786 C787 = CAP_SMD_POL_0: Tolerance: TOL; User Part Number: ECS-T0JD227R; part number: CAP_SMD_POL_0-220UF,5%,6.3V,CAPT_7343
C26 C27 C33-C40 C43 C46 C49 C56 C58 C59 C61 C66-C71 C74-C76 C78 C79 C85 C91 C103 C129 C140 C144 C149-C164 C166 C170 C173 C175 C177 C179 C181 C184 C185 C187 C189-C195 C199-C204 C211-C213 C215-C217 C219 C227 C234 C235 C241-C246 C248 C250-C255 C258 C260 C262 C264-C272 C275 C278 C281 C285 C286 C289 C293 C299 C300 C304-C306 C309 C316 C318 C320-C322 C330 C332-C335 C337 C339 C343 C344 C346 C349 C353 C355 C356 C361 C362 C367 C368 C373 C375 C376 C379 C381-C384 C386 C389 C391-C393 C395-C397 C400 C402 C404-C407 C410 C419 C420 C422 C423 C434 C437 C440-C446 C448-C450 C453-C457 C465 C468 C471 C473 C474 C476 C478 C479 C483 C486 C487 C489 C491 C492 C494 C503 C504 C506-C512 C514-C516 C523 C524 C527-C530 C533-C535 C539 C541 C542 C545 C547-C549 C552 C554 C556 C558 C560 C561 C563 C565 C569 C570 C573-C577 C580 C582 C585 C587 C589 C592 C594 C595 C597 C598 C600 C603 C606 C607 C609 C611 C612 C614 C617-C619 C621-C625 C628-C635 C637 C639 C641 C649 C650 C658 C671 C728 C730 C732 = CAP_SMD_NPOL_0: Tolerance: XXX; User Part Number: ECJ-1VB1C103K; part number: CAP_SMD_NPOL_0-0.01UF,5%,CAP_0603
C28 C73 = CAP_SMD_POL_0: User Part Number: 4SP820M; Tolerance: XXX; part number: CAP_SMD_POL_0-820UF,5%,4V,CAP_SP
C41 C47 C136-C139 C206 C207 C229 C231 C236 C303 C314 C329 C364-C366 C398 C399 C411-C413 C427 C428 C438 C459 C463 C559 C586 C616 C627 C776 = CAP_SMD_NPOL_0: Tolerance: XXX; User Part Number: TAJA225K010R; part number: CAP_SMD_NPOL_0-2.2UF,5%,CAP_0805
C42 C57 = CAP_SMD_POL_0: User Part Number: 6SP680M; Tolerance: XXX; part number: CAP_SMD_POL_0-680UF,5%,6.3V,CAP_SP
C48 = CAP_SMD_NPOL_0: User Part Number: ECJ3YB2A473K; Tolerance: XXX; part number: CAP_SMD_NPOL_0-0.047UF,5%,CAP_1206
C62-C65 = CAP_SMD_NPOL_0: Tolerance: XXX; User Part Number: ECJ-1VB1C473K; part number: CAP_SMD_NPOL_0-0.047UF,5%,CAP_0603
C81 = CAP_SMD_NPOL_0: Tolerance: XXX; User Part Number: ECJ-1VB1C622K; part number: CAP_SMD_NPOL_0-6200PF,5%,CAP_0603
C82 = CAP_SMD_NPOL_0: Tolerance: XXX; User Part Number: ECJ-1VB1C121K; part number: CAP_SMD_NPOL_0-120PF,5%,CAP_0603
C86 C95 C564 C567 = CAP_SMD_POL_0: User Part Number: JMK212BJ106MG; Tolerance: XXX; part number: CAP_SMD_POL_0-10UF,5%,10V,CAP_1206
C88 C94 C96-C99 C106-C109 C711-C713 = CAP_SMD_NPOL_0: Tolerance: XXX; User Part Number: ECJ-1VB1H102K; part number: CAP_SMD_NPOL_0-0.001UF,5%,CAP_0402
C93 C167 C232 C313 C425 C777 C790 = CAP_SMD_NPOL_0: Tolerance: XXX; User Part Number: ECJ-2FF1E105Z; part number: CAP_SMD_NPOL_0-1.0UF,5%,CAP_0805
C100 C124 = CAP_SMD_NPOL_0: User Part Number: ECJ-3YB2A104K; Tolerance: XXX; part number: CAP_SMD_NPOL_0-0.1UF,5%,CAP_1206
C121 C123 = CAP_SMD_POL_0: Tolerance: TOL; User Part Number: ECS-T1AD476R; part number: CAP_SMD_POL_0-47UF,5%,16V,CAPT_7343
C126 C128 C681-C683 = CAP_SMD_NPOL_0: Tolerance: XXX; User Part Number: ECJ-2VF1C105Z; part number: CAP_SMD_NPOL_0-1UF,5%,CAP_0805
C130 C132 C142 C168 C208 C233 C259 C263 C291 C292 C324 C341 C359 C416 C417 C431 C432 C435 C436 C460-C462 C490 C519 = CAP_SMD_NPOL_0: Tolerance: XXX; User Part Number: ECJ-1VB1H102K; part number: CAP_SMD_NPOL_0-0.001UF,5%,CAP_0603
C131 = CAP_SMD_POL_0: Tolerance: TOL; User Part Number: ECS-T1DD336R; part number: CAP_SMD_POL_0-33UF,5%,20V,CAPT_7343
C133 = CAP_SMD_NPOL_0: Tolerance: XXX; User Part Number: ECJ-0EB1H101K; part number: CAP_SMD_NPOL_0-100PF,5%,CAP_0603
C145 C146 C696 C697 C734 C736 = CAP_SMD_POL_0: User Part Number: ECS-T0JX476RABC; Tolerance: TOL; part number: CAP_SMD_POL_0-47UF,5%,6.3V,CAPT_3528
C209 C680 = CAP_SMD_POL_0: Tolerance: TOL; User Part Number: ECS-T0JX476RABC; part number: CAP_SMD_POL_0-47UF,5%,6.3V,CAPT_7343
C307 = CAP_SMD_NPOL_0: Tolerance: XXX; User Part Number: ECJ-0EB1H101K; part number: CAP_SMD_NPOL_0-100PF,5%,CAP_0402
C308 C317 C328 = CAP_SMD_NPOL_0: Tolerance: XXX; User Part Number: ECJ-0EB1A104K; part number: CAP_SMD_NPOL_0-0.1UF,5%,CAP_0402
C418 = CAP_SMD_NPOL_0: Tolerance: XXX; User Part Number: ECJ-1VC1H471J; part number: CAP_SMD_NPOL_0-470PF,5%,CAP_0603
C638 = CAP_SMD_NPOL_0: Tolerance: XXX; User Part Number: ECJ-1VBC1C103K; part number: CAP_SMD_NPOL_0-10PF,5%,CAP_0603
C714 = CAP_SMD_POL_0: User Part Number: TPSC107K010R0075; Tolerance: TOL; part number: CAP_SMD_POL_0-100UF,5%,10V,CAPT_C
C716 C717 C782-C785 C788 C789 = CAP_SMD_POL_0: Tolerance: TOL; User Part Number: TPSC107K010R0075; part number: CAP_SMD_POL_0-100UF,5%,10V,CAPT_7343
C727 C729 C731 = CAP_SMD_POL_0: User Part Number: ECS-T1AD476R; Tolerance: TOL; part number: CAP_SMD_POL_0-47UF,5%,16V,CAPT_3528
C754 C758 C762 C766 C770 C778 = CAP_SMD_NPOL_0: Tolerance: XXX; User Part Number: ECJ-0EB1E471K; part number: CAP_SMD_NPOL_0-470PF,10%,CAP_0402
C755 C759 C763 C767 C771 C779 = CAP_SMD_NPOL_0: Tolerance: XXX; User Part Number: ECJ-0EB1C103K; part number: CAP_SMD_NPOL_0-0.001UF,10%,CAP_0402
C756 C760 C764 C768 C772 C780 = CAP_SMD_NPOL_0: Tolerance: XXX; User Part Number: ECJ-0EB1A104K; part number: CAP_SMD_NPOL_0-0.1UF,10%,CAP_0402
C757 C761 C765 C769 C773 C781 = CAP_SMD_NPOL_0: User Part Number: GRM188R60J225KE01D; Tolerance: XXX; part number: CAP_SMD_NPOL_0-2.2UF,10%,CAPT_0603
C774 = CAP_SMD_NPOL_0: Tolerance: XXX; User Part Number: ECJ-1VB1H102K; part number: CAP_SMD_NPOL_0-0.001UF,10%,CAP_0603
C775 = CAP_SMD_NPOL_0: Tolerance: XXX; User Part Number: ECJ-0EB1E471K; part number: CAP_SMD_NPOL_0-470PF,5%,CAP_0402
CN1-CN13 = CAPACITOR NETWORK_3: Tolerance: XXX; User Part Number: ECJ-RVF1E104Z; part number: CAPACITOR NETWORK_3-0.1UF,5%
CON3 = CF_HEADER_0: User Part Number: INV; Tolerance: TOL
HS1 HS2 = HEAT SINK_TO-263_1
ISO1 = OPTO ISOLATOR-A_0
J1 J108 J109 = HM-ZD-40(P)_0
J2-J6 J16-J20 J24-J30 J37 J43 J46 J47 J49 J52 J60-J62 J69 J76 J80 J83 J84 J88 J89 J91 J94 J95 J97 J99 J100 J102-J104 J106 J107 J121 J122 = LTI-SASF54GT_0
J11 J15 J23 J32 = 1364532-2_2
J31 = CONN PCB 10X2_0
J34 J75 = 2-767004-2_0
J36 = HEADER 4X2: Tolerance: TOL; User Part Number: INV
J38 J45 J54 J64 = 437-001_12
J42 J59 = TMP_201136
J48 J55 J56 J90 J111-J114 = CON2
J53 J68 = CON20A
J57 J58 = AGILENT_E5387A
J63 J85 J87 = CONN PCB 5X2-S
J72 J77 J81 J86 J93 J98 J101 J105 = SMA_EDGE_LAUNCH_13
J78 = HDR2X10
J79 = HDR2X7
J92 = HDR2X20
J123 = HEADER 2X2: Tolerance: TOL; User Part Number: INV
J124 = CONN_DSUB_9PIN_DOUBLE_5
PMCJN1 = HEADER 32X2_0
PMCJN2 = HEADER 32X2_1
R1 R136 = R: User Part Number: ERJ-2GEJ56X; Tolerance: XXX; part number: R-56,2%,RES_0402; signal model: DEFAULT_RESISTOR_56.000000OHM_1_2
R2 = R: User Part Number: NPR1TTE56LJ; Tolerance: XXX; part number: R-0.056,5%,THRU_HOLE
R3 R6 R18 R33 R43 R60 R61 R86 R135 R137 R138 R150-R157 R165 R167 R168 R214 R270-R277 R322 R323 R342 R343 R346 R347 = R: User Part Number: NRC04F1000TR; Tolerance: XXX; part number: R-100,2%,RES_0402
R4 = R: User Part Number: NRC06F1040TR; Tolerance: XXX; part number: R-104,5%,RES_0603
R5 = R: User Part Number: NRC06F20R0TR; Tolerance: XXX; part number: R-20,5%,RES_0603
R7 R11 R23 R30 R70 R73 R236 R238 = R: User Part Number: NRC06F56R0TR; Tolerance: XXX; part number: R-56,2%,RES_0603; signal model: DEFAULT_RESISTOR_56.000000OHM_1_2
R15 R87 R90 R91 R94 R192 R193 R195 = R: User Part Number: NRC04F1400TR; Tolerance: XXX; part number: R-104,5%,RES_0402
R16 R88 R89 R92 R93 R191 R194 R196 = R: User Part Number: NRC04F78R7TR; Tolerance: XXX; part number: R-78.7,5%,RES_0402
R17 = R: User Part Number: NRC04F6651TR; Tolerance: XXX; part number: R-6.65K,5%,RES_0402
R19 = R: User Part Number: NRC04F4421TR; Tolerance: XXX; part number: R-4.42K,5%,RES_0402
R21 R344 = R: User Part Number: NRC04Z0; Tolerance: XXX; part number: R-0,5%,RES_0402
R27 R35 R40 R46-R48 = R: User Part Number: NRC04F1620TR; Tolerance: XXX; part number: R-162,5%,RES_0402
R28 R31 R32 R74 R75 R225 = R: User Part Number: NRC04J1001TR; Tolerance: XXX; part number: R-1.0K,5%,RES_0402
R34 = R: User Part Number: NRC04F2701TR; Tolerance: XXX; part number: R-2.7K,5%,RES_0402
R37 R42 R51 R55 R76 R77 R98 R123 R133 R142-R148 R158 R216 R231-R233 R279-R281 R289-R294 R304 R318 R319 R358-R360 = R: User Part Number: NRC06J1002TR; Tolerance: XXX; part number: R-10.0K,5%,RES_0603
R39 R41 R44 R53 R56 R57 R68 R119 R120 R130 R140 R159 R160 R163 R164 R169 R170 R172 R207 R247 R260 R262-R269 R278 R282-R286 R296 R299 R303 R305 = R: User Part Number: NRC06J1001TR; Tolerance: XXX; part number: R-1.0K,5%,RES_0603
R52 R127 = R: User Part Number: NRC04J220TR; Tolerance: XXX; part number: R-22,5%,RES_0402
R62 R71 R190 R202 = R: User Part Number: NRC06J4R7TR; Tolerance: XXX; part number: R-4.7,5%,RES_0603
R65-R67 R80-R85 R99 R100 = R: User Part Number: NRC06J2501TR; Tolerance: XXX; part number: R-2.5K,2%,RES_0603
R101 = R: User Part Number: NRC06J2001TR; Tolerance: XXX; part number: R-2.0K,5%,RES_0603
R102 R121 R125 R128 = R: User Part Number: NRC06J1102TR; Tolerance: XXX; part number: R-11.0K,5%,RES_0603
R103 R104 R116 R118 = R: User Part Number: ERJ3EKF24.9V; Tolerance: XXX; part number: R-24.9,5%,RES_0603
R105-R114 = R: User Part Number: NRC06J6003TR; Tolerance: XXX; part number: R-60.0K,5%,RES_0603
R115 = R: User Part Number: NRC06F4990TR; Tolerance: XXX; part number: R-499,5%,RES_0603
R117 = R: User Part Number: NRC06F2202TR; Tolerance: XXX; part number: R-22K,5%,RES_0603
R122 = R: User Part Number: NRC06F3002TR; Tolerance: XXX; part number: R-30K,5%,RES_0603
R124 R204 = R: User Part Number: NRC06J2000TR; Tolerance: XXX; part number: R-200,2%,RES_0603
R126 R149 R171 R180-R184 R186 R203 R208 R212 R345 R355 = R: User Part Number: NRC04F1000TR; Tolerance: XXX; part number: R-NI,5%,RES_0402
R129 = R: User Part Number: NRC04J230TR; Tolerance: XXX; part number: R-23,5%,RES_0603
R131 R132 R242 = R: User Part Number: NRC06F2500TR; Tolerance: XXX; part number: R-250,2%,RES_0603
R134 R261 R298 R300 R301 = R: User Part Number: NRC06J47R0TR; Tolerance: XXX; part number: R-47,5%,RES_0603
R139 R141 = R: User Part Number: NRC06F49R9TR; Tolerance: XXX; part number: R-49.9,2%,RES_0603
R161 R162 R173 R174 R205 R206 R209-R211 R217-R221 R224 R226-R230 R235 R237 R239 R241 = R: User Part Number: NRC06J4701TR; Tolerance: XXX; part number: R-4.7K,5%,RES_0603
R175 = R: User Part Number: EXB-2HV102JV; Tolerance: XXX; part number: R-20.0K,5%,RES_0603
R176 R177 R243 R244 = R: User Part Number: NRC04F49R9TR; Tolerance: XXX; part number: R-49.9,5%,RES_0402
R178 R179 R259 R324 R326 R327 R334-R337 R348 R349 R361 = R: User Part Number: NRC06Z0; Tolerance: XXX; part number: R-0,5%,RES_0603
R185 = R: Tolerance: XXX; User Part Number: NRC10F2000TR; part number: R-200,5%,RES_0805
R187 = R: Tolerance: XXX; User Part Number: NRC10F2260TR; part number: R-226,5%,RES_0805
R189 = R: Tolerance: XXX; User Part Number: NRC04F1002TR; part number: R-10K,5%,RES_0805
R215 = R: User Part Number: NRC04F1002TR; Tolerance: XXX; part number: R-10K,5%,RES_0402
R222 = R: User Part Number: ERJ-2RKF93.10V; Tolerance: XXX; part number: R-93,5%,RES_0603
R223 = R: User Part Number: ERJ-2RKF158.0V; Tolerance: XXX; part number: R-158,5%,RES_0603
R248 = R: User Part Number: NRC06F7870TR; Tolerance: XXX; part number: R-787,5%,RES_0603
R249-R258 = R: User Part Number: NRC06F1502TR; Tolerance: XXX; part number: R-15.0K,5%,RES_0603
R297 = R: User Part Number: NRC06F7870TR; Tolerance: XXX; part number: R-78.7,5%,RES_0603
R306 R307 R353 = R: User Part Number: NRC06J5601TR; Tolerance: XXX; part number: R-5.6K,5%,RES_0603
R329-R333 R338-R341 R350 R351 = R: User Part Number: NRC06J1002TR; Tolerance: XXX; part number: R-NI,5%,RES_0603
R352 = R: Tolerance: XXX; User Part Number: ERJ-6GEYJ754V; part number: R-750K,5%,RES_0805
R354 = R: User Part Number: NRC06J3001TR; Tolerance: XXX; part number: R-3.0K,5%,RES_0603
R357 = R: User Part Number: NRC06J6201TR; Tolerance: XXX; part number: R-6.2K,5%,RES_0603
RJ1 = RJ45INTLED_0
RN5 RN23-RN32 = RES_PACK: Tolerance: XXX; User Part Number: EXB-2HV560JV; part number: RES_PACK-56,5%; signal model: DEFAULT_RESISTOR_PACK_8_56.000000OHM
RN14 RN37-RN39 = RES_PACK: Tolerance: XXX; User Part Number: EXB-2HV102JV; part number: RES_PACK-1.0K,5%
RN15-RN18 = RES_PACK: User Part Number: EXB-2HV103JV; Tolerance: XXX; part number: RES_PACK-10K,5%
RN19 RN20 = RES_PACK: User Part Number: EXB-2HV103JV; Tolerance: XXX; part number: RES_PACK-10.0K,5%
RN21 RN22 RN33-RN36 = RES_PACK: User Part Number: EXB-2HV221JV; Tolerance: XXX; part number: RES_PACK-220,5%
U1 U42 = MIC29502BU_1
U2 = LM1587_0
U4 = MC100EP33_0
U5 U12 = MAX1619_4
U6 = MC100EP139_0
U7 = U7_EP2S60F1020: User Part Number: u7_ep2s60f1020; signal model: StratixII
U8 = QD48T033050_0
U9 = MC100EPT26_0: User Part Number: INV; Tolerance: TOL
U10 = ICS87946-01_4
U11 = LAN91C111_2
U13 = ICS8304AM
U14 = MAX1953_1
U15 = EP1S40F1020_5
U17 = FDS6898A
U18 U32 = ICS8545_TSSOP_0
U19-U21 = QS32X2245/SO_6
U22-U24 U39 U52 = QS3861/SO_2
U25 U26 U34 = 74ALVCH16244_2
U27 = XENPAK_1
U28 U33 = LTC1386_0
U29 U30 = EPC16U_PQFP100
U31 = AM29DL640D
U36 U37 = FAN5066_0
U38 = MIC5209BM: Tolerance: TOL; User Part Number: INV
U43 U44 = MC14490: Tolerance: TOL; User Part Number: INV
U45 = QD48T20050_2
U46 U47 = ICS83026I_2
U53 = LP2995M
U59 = FDC6323L_0: Tolerance: TOL; User Part Number: INV
U60 = MIC5219BM5_1: Tolerance: TOL; User Part Number: INV
XU2 = PARALLELBUS_DIMM
Y1-Y3 = CRYSTAL1-4/SM_1
Y4 = OSC_SMT

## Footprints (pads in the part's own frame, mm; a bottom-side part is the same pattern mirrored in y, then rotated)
4P_OSC
  rect 2.032x1.829 smd: 1(-2.1,2.54) 2(-2.1,-2.54) 3(2.1,-2.54) 4(2.1,2.54)
8_PINS_SURFACE_MOUNT
  rect 1.143x0.559 smd: 1(-0.762,1.2) 2(-0.762,0.4) 3(-0.762,-0.4) 4(-0.762,-1.2) 5(0.762,-1.2) 6(0.762,-0.4) 7(0.762,0.4) 8(0.762,1.2)
10_PIN_CONNECTOR
  rect 3.175x1.27 smd: 1(-2.731,5.08) 2(2.731,5.08) 3(-2.731,2.54) 4(2.731,2.54) 5(-2.731,0) 6(2.731,0) 7(-2.731,-2.54) 8(2.731,-2.54) 9(-2.731,-5.08) 10(2.731,-5.08)
16_PIN_SMD
  rect 0.889x0.432 smd: 1(-0.944,1.839) 8(-0.944,-1.839) 9(0.944,-1.839) 16(0.944,1.839)
  rect 0.889x0.254 smd: 2(-0.944,1.25) 3(-0.944,0.75) 4(-0.944,0.25) 5(-0.944,-0.25) 6(-0.944,-0.75) 7(-0.944,-1.25) 10(0.944,-1.25) 11(0.944,-0.75) 12(0.944,-0.25) 13(0.944,0.25) 14(0.944,0.75) 15(0.944,1.25)
BRICK7
  rect 2.54x2.54 hole 1.575: 1(0,0)
  round 2.54 hole 1.575: 2(0,-8.89) 3(0,-17.78) 4(50.8,-18.415) 5(50.8,-12.065) 6(50.8,-5.715) 7(50.8,0.635)
BRICK_8
  rect 2.54x2.54 hole 1.575: 1(0,0)
  round 2.54 hole 1.575: 2(0,-7.62) 3(0,-15.24) 5(50.8,-11.43) 6(50.8,-7.62) 7(50.8,-3.81)
  round 3.099 hole 2.159: 4(50.8,-15.24) 8(50.8,0)
CAP_0402
  rect 0.508x0.508 smd: 1(0,0.445) 2(0,-0.445)
CAP_0603
  rect 0.813x1.067 smd: 1(0,0.85) 2(0,-0.85)
CAP_0805
  rect 1.6x1.321 smd: 1(0,0.95) 2(0,-0.95)
CAP_1206
  rect 1.778x1.6 smd: 1(0,1.4) 2(0,-1.4)
CAP_SP
  rect 1.524x1.524 hole 1.067: 1(0,0)
  round 1.524 hole 1.067: 2(0,-5)
CAPT_0603
  rect 0.813x1.067 smd: 1(0,0.85) 2(0,-0.85)
CAPT_3528
  rect 2.032x2.286 smd: 1(-1.524,0) 2(1.524,0)
CAPT_7343
  rect 2.54x3.556 smd: 1(-3.302,0) 2(3.302,0)
CAPT_C
  rect 2.032x2.794 smd: 1(-2.286,0) 2(2.286,0)
CFCONN50P
  rect 2.489x5.994 smd: (-22.86,-12.532) (22.86,-12.532)
  round 0.127 hole 1.194 unplated: (-21.828,5.593) (21.828,5.593)
  round 0.127 hole 2.286 unplated: (-20.491,3.216) (20.491,3.216)
  rect 0.432x1.981 smd: 1(-15.557,5.791) 2(-14.287,5.791) 3(-13.018,5.791) 4(-11.748,5.791) 5(-10.477,5.791) 6(-9.207,5.791) 7(-7.938,5.791) 8(-6.668,5.791) 9(-5.397,5.791) 10(-4.128,5.791) 11(-2.857,5.791) 12(-1.587,5.791) 13(-0.318,5.791) 14(0.953,5.791) 15(2.223,5.791) 16(3.493,5.791) 17(4.763,5.791) 18(6.032,5.791) 19(7.303,5.791) 20(8.572,5.791) 21(9.842,5.791) 22(11.113,5.791) 23(12.383,5.791) 24(13.652,5.791) 25(14.922,5.791) 26(-14.922,5.791) 27(-13.652,5.791) 28(-12.383,5.791) 29(-11.113,5.791) 30(-9.842,5.791) 31(-8.572,5.791) 32(-7.303,5.791) 33(-6.032,5.791) 34(-4.763,5.791) 35(-3.493,5.791) 36(-2.223,5.791) 37(-0.953,5.791) 38(0.318,5.791) 39(1.587,5.791) 40(2.857,5.791) 41(4.128,5.791) 42(5.397,5.791) 43(6.668,5.791) 44(7.938,5.791) 45(9.207,5.791) 46(10.477,5.791) 47(11.748,5.791) 48(13.018,5.791) 49(14.287,5.791) 50(15.557,5.791)
CON120_HM-ZD
  rect 1.118x1.118 hole 0.61: 1A(0,0)
  round 1.118 hole 0.61: 1B(0,1.5) 1BG(0,3) 1C(0,4.5) 1D(0,6) 1DG(0,7.5) 1E(0,9) 1F(0,10.5) 1FG(0,12) 1G(0,13.5) 1H(0,15) 1HG(0,16.5) 2A(-2.5,0) 2B(-2.5,1.5) 2BG(-2.5,3) 2C(-2.5,4.5) 2D(-2.5,6) 2DG(-2.5,7.5) 2E(-2.5,9) 2F(-2.5,10.5) 2FG(-2.5,12) 2G(-2.5,13.5) 2H(-2.5,15) 2HG(-2.5,16.5) 3A(-5,0) 3B(-5,1.5) 3BG(-5,3) 3C(-5,4.5) 3D(-5,6) 3DG(-5,7.5) 3E(-5,9) 3F(-5,10.5) 3FG(-5,12) 3G(-5,13.5) 3H(-5,15) 3HG(-5,16.5) 4A(-7.5,0) 4B(-7.5,1.5) 4BG(-7.5,3) 4C(-7.5,4.5) 4D(-7.5,6) 4DG(-7.5,7.5) 4E(-7.5,9) 4F(-7.5,10.5) 4FG(-7.5,12) 4G(-7.5,13.5) 4H(-7.5,15) 4HG(-7.5,16.5) 5A(-10,0) 5B(-10,1.5) 5BG(-10,3) 5C(-10,4.5) 5D(-10,6) 5DG(-10,7.5) 5E(-10,9) 5F(-10,10.5) 5FG(-10,12) 5G(-10,13.5) 5H(-10,15) 5HG(-10,16.5) 6A(-12.5,0) 6B(-12.5,1.5) 6BG(-12.5,3) 6C(-12.5,4.5) 6D(-12.5,6) 6DG(-12.5,7.5) 6E(-12.5,9) 6F(-12.5,10.5) 6FG(-12.5,12) 6G(-12.5,13.5) 6H(-12.5,15) 6HG(-12.5,16.5) 7A(-15,0) 7B(-15,1.5) 7BG(-15,3) 7C(-15,4.5) 7D(-15,6) 7DG(-15,7.5) 7E(-15,9) 7F(-15,10.5) 7FG(-15,12) 7G(-15,13.5) 7H(-15,15) 7HG(-15,16.5) 8A(-17.5,0) 8B(-17.5,1.5) 8BG(-17.5,3) 8C(-17.5,4.5) 8D(-17.5,6) 8DG(-17.5,7.5) 8E(-17.5,9) 8F(-17.5,10.5) 8FG(-17.5,12) 8G(-17.5,13.5) 8H(-17.5,15) 8HG(-17.5,16.5) 9A(-20,0) 9B(-20,1.5) 9BG(-20,3) 9C(-20,4.5) 9D(-20,6) 9DG(-20,7.5) 9E(-20,9) 9F(-20,10.5) 9FG(-20,12) 9G(-20,13.5) 9H(-20,15) 9HG(-20,16.5) 10A(-22.5,0) 10B(-22.5,1.5) 10BG(-22.5,3) 10C(-22.5,4.5) 10D(-22.5,6) 10DG(-22.5,7.5) 10E(-22.5,9) 10F(-22.5,10.5) 10FG(-22.5,12) 10G(-22.5,13.5) 10H(-22.5,15) 10HG(-22.5,16.5)
DB9DOUBLE
  rect 1.905x1.905 hole 1.245: 1(-0.051,0) 10(-0.051,6.604)
  round 1.905 hole 1.245: 2(2.718,0) 3(5.486,0) 4(8.255,0) 5(11.024,0) 6(1.333,2.845) 7(4.102,2.845) 8(6.871,2.845) 9(9.639,2.845) 11(2.718,6.604) 12(5.486,6.604) 13(8.255,6.604) 14(11.024,6.604) 15(1.333,9.449) 16(4.102,9.449) 17(6.871,9.449) 18(9.639,9.449)
  round 7.62 hole 3.048: 19(-7.01,1.422) 20(17.983,1.422) 21(-7.01,9.423) 22(17.983,9.423)
DIMM240
  round 3.81 hole 2.438: (-73,0) (0,0) (65,0)
  rect 1.27x1.27 hole 0.711: 1(-65.5,-0.95)
  round 1.27 hole 0.711: 2(-64.5,-2.85) 3(-63.5,-0.95) 4(-62.5,-2.85) 5(-61.5,-0.95) 6(-60.5,-2.85) 7(-59.5,-0.95) 8(-58.5,-2.85) 9(-57.5,-0.95) 10(-56.5,-2.85) 11(-55.5,-0.95) 12(-54.5,-2.85) 13(-53.5,-0.95) 14(-52.5,-2.85) 15(-51.5,-0.95) 16(-50.5,-2.85) 17(-49.5,-0.95) 18(-48.5,-2.85) 19(-47.5,-0.95) 20(-46.5,-2.85) 21(-45.5,-0.95) 22(-44.5,-2.85) 23(-43.5,-0.95) 24(-42.5,-2.85) 25(-41.5,-0.95) 26(-40.5,-2.85) 27(-39.5,-0.95) 28(-38.5,-2.85) 29(-37.5,-0.95) 30(-36.5,-2.85) 31(-35.5,-0.95) 32(-34.5,-2.85) 33(-33.5,-0.95) 34(-32.5,-2.85) 35(-31.5,-0.95) 36(-30.5,-2.85) 37(-29.5,-0.95) 38(-28.5,-2.85) 39(-27.5,-0.95) 40(-26.5,-2.85) 41(-25.5,-0.95) 42(-24.5,-2.85) 43(-23.5,-0.95) 44(-22.5,-2.85) 45(-21.5,-0.95) 46(-20.5,-2.85) 47(-19.5,-0.95) 48(-18.5,-2.85) 49(-17.5,-0.95) 50(-16.5,-2.85) 51(-15.5,-0.95) 52(-14.5,-2.85) 53(-13.5,-0.95) 54(-12.5,-2.85) 55(-11.5,-0.95) 56(-10.5,-2.85) 57(-9.5,-0.95) 58(-8.5,-2.85) 59(-7.5,-0.95) 60(-6.5,-2.85) 61(-5.5,-0.95) 62(-4.5,-2.85) 63(-3.5,-0.95) 64(-2.5,-2.85) 65(2.5,-0.95) 66(3.5,-2.85) 67(4.5,-0.95) 68(5.5,-2.85) 69(6.5,-0.95) 70(7.5,-2.85) 71(8.5,-0.95) 72(9.5,-2.85) 73(10.5,-0.95) 74(11.5,-2.85) 75(12.5,-0.95) 76(13.5,-2.85) 77(14.5,-0.95) 78(15.5,-2.85) 79(16.5,-0.95) 80(17.5,-2.85) 81(18.5,-0.95) 82(19.5,-2.85) 83(20.5,-0.95) 84(21.5,-2.85) 85(22.5,-0.95) 86(23.5,-2.85) 87(24.5,-0.95) 88(25.5,-2.85) 89(26.5,-0.95) 90(27.5,-2.85) 91(28.5,-0.95) 92(29.5,-2.85) 93(30.5,-0.95) 94(31.5,-2.85) 95(32.5,-0.95) 96(33.5,-2.85) 97(34.5,-0.95) 98(35.5,-2.85) 99(36.5,-0.95) 100(37.5,-2.85) 101(38.5,-0.95) 102(39.5,-2.85) 103(40.5,-0.95) 104(41.5,-2.85) 105(42.5,-0.95) 106(43.5,-2.85) 107(44.5,-0.95) 108(45.5,-2.85) 109(46.5,-0.95) 110(47.5,-2.85) 111(48.5,-0.95) 112(49.5,-2.85) 113(50.5,-0.95) 114(51.5,-2.85) 115(52.5,-0.95) 116(53.5,-2.85) 117(54.5,-0.95) 118(55.5,-2.85) 119(56.5,-0.95) 120(57.5,-2.85) 121(-65.5,2.85) 122(-64.5,0.95) 123(-63.5,2.85) 124(-62.5,0.95) 125(-61.5,2.85) 126(-60.5,0.95) 127(-59.5,2.85) 128(-58.5,0.95) 129(-57.5,2.85) 130(-56.5,0.95) 131(-55.5,2.85) 132(-54.5,0.95) 133(-53.5,2.85) 134(-52.5,0.95) 135(-51.5,2.85) 136(-50.5,0.95) 137(-49.5,2.85) 138(-48.5,0.95) 139(-47.5,2.85) 140(-46.5,0.95) 141(-45.5,2.85) 142(-44.5,0.95) 143(-43.5,2.85) 144(-42.5,0.95) 145(-41.5,2.85) 146(-40.5,0.95) 147(-39.5,2.85) 148(-38.5,0.95) 149(-37.5,2.85) 150(-36.5,0.95) 151(-35.5,2.85) 152(-34.5,0.95) 153(-33.5,2.85) 154(-32.5,0.95) 155(-31.5,2.85) 156(-30.5,0.95) 157(-29.5,2.85) 158(-28.5,0.95) 159(-27.5,2.85) 160(-26.5,0.95) 161(-25.5,2.85) 162(-24.5,0.95) 163(-23.5,2.85) 164(-22.5,0.95) 165(-21.5,2.85) 166(-20.5,0.95) 167(-19.5,2.85) 168(-18.5,0.95) 169(-17.5,2.85) 170(-16.5,0.95) 171(-15.5,2.85) 172(-14.5,0.95) 173(-13.5,2.85) 174(-12.5,0.95) 175(-11.5,2.85) 176(-10.5,0.95) 177(-9.5,2.85) 178(-8.5,0.95) 179(-7.5,2.85) 180(-6.5,0.95) 181(-5.5,2.85) 182(-4.5,0.95) 183(-3.5,2.85) 184(-2.5,0.95) 185(2.5,2.85) 186(3.5,0.95) 187(4.5,2.85) 188(5.5,0.95) 189(6.5,2.85) 190(7.5,0.95) 191(8.5,2.85) 192(9.5,0.95) 193(10.5,2.85) 194(11.5,0.95) 195(12.5,2.85) 196(13.5,0.95) 197(14.5,2.85) 198(15.5,0.95) 199(16.5,2.85) 200(17.5,0.95) 201(18.5,2.85) 202(19.5,0.95) 203(20.5,2.85) 204(21.5,0.95) 205(22.5,2.85) 206(23.5,0.95) 207(24.5,2.85) 208(25.5,0.95) 209(26.5,2.85) 210(27.5,0.95) 211(28.5,2.85) 212(29.5,0.95) 213(30.5,2.85) 214(31.5,0.95) 215(32.5,2.85) 216(33.5,0.95) 217(34.5,2.85) 218(35.5,0.95) 219(36.5,2.85) 220(37.5,0.95) 221(38.5,2.85) 222(39.5,0.95) 223(40.5,2.85) 224(41.5,0.95) 225(42.5,2.85) 226(43.5,0.95) 227(44.5,2.85) 228(45.5,0.95) 229(46.5,2.85) 230(47.5,0.95) 231(48.5,2.85) 232(49.5,0.95) 233(50.5,2.85) 234(51.5,0.95) 235(52.5,2.85) 236(53.5,0.95) 237(54.5,2.85) 238(55.5,0.95) 239(56.5,2.85) 240(57.5,0.95)
DIP8
  rect 1.524x1.524 hole 1.067: 1(0,0)
  round 1.524 hole 1.067: 2(0,-2.54) 3(0,-5.08) 4(0,-7.62) 5(7.62,-7.62) 6(7.62,-5.08) 7(7.62,-2.54) 8(7.62,0)
EDGE_LAUNCHED_SMA
  rect 1.778x0.635 smd: 1(0,0)
  round 2.667 hole 2.159: 2(-1.795,4.755) 3(-1.795,-4.745)
  round 0.914 hole 0.533: 4(0.435,-1.146) 5(0.435,1.146) 6(-0.835,-1.146) 7(-0.835,1.146) 8(-2.545,1.165) 9(-4.035,1.245) 10(0.435,2.515) 11(-1.055,2.515) 12(-2.545,2.515) 13(-4.035,2.515) 14(-4.035,4.005) 15(0.435,4.005) 16(-4.035,5.495) 17(0.435,5.495) 18(-4.035,6.985) 19(-2.545,6.985) 20(-1.055,6.985) 21(0.435,6.985) 22(-4.035,-1.245) 23(-2.545,-1.165) 24(-4.035,-2.515) 25(-2.545,-2.515) 26(-1.055,-2.515) 27(0.435,-2.515) 28(-4.035,-4.005) 29(0.435,-4.005) 30(-4.035,-5.495) 31(0.435,-5.495) 32(-4.035,-6.985) 33(-2.545,-6.985) 34(-1.055,-6.985) 35(0.435,-6.985)
F1020
  round 0.457 smd: A2(-14.5,15.5) A3(-13.5,15.5) A4(-12.5,15.5) A5(-11.5,15.5) A6(-10.5,15.5) A7(-9.5,15.5) A8(-8.5,15.5) A9(-7.5,15.5) A10(-6.5,15.5) A11(-5.5,15.5) A12(-4.5,15.5) A13(-3.5,15.5) A14(-2.5,15.5) A15(-1.5,15.5) A16(-0.5,15.5) A17(0.5,15.5) A18(1.5,15.5) A19(2.5,15.5) A20(3.5,15.5) A21(4.5,15.5) A22(5.5,15.5) A23(6.5,15.5) A24(7.5,15.5) A25(8.5,15.5) A26(9.5,15.5) A27(10.5,15.5) A28(11.5,15.5) A29(12.5,15.5) A30(13.5,15.5) A31(14.5,15.5) AA1(-15.5,-4.5) AA2(-14.5,-4.5) AA3(-13.5,-4.5) AA4(-12.5,-4.5) AA5(-11.5,-4.5) AA6(-10.5,-4.5) AA7(-9.5,-4.5) AA8(-8.5,-4.5) AA9(-7.5,-4.5) AA10(-6.5,-4.5) AA11(-5.5,-4.5) AA12(-4.5,-4.5) AA13(-3.5,-4.5) AA14(-2.5,-4.5) AA15(-1.5,-4.5) AA16(-0.5,-4.5) AA17(0.5,-4.5) AA18(1.5,-4.5) AA19(2.5,-4.5) AA20(3.5,-4.5) AA21(4.5,-4.5) AA22(5.5,-4.5) AA23(6.5,-4.5) AA24(7.5,-4.5) AA25(8.5,-4.5) AA26(9.5,-4.5) AA27(10.5,-4.5) AA28(11.5,-4.5) AA29(12.5,-4.5) AA30(13.5,-4.5) AA31(14.5,-4.5) AA32(15.5,-4.5) AB1(-15.5,-5.5) AB2(-14.5,-5.5) AB3(-13.5,-5.5) AB4(-12.5,-5.5) AB5(-11.5,-5.5) AB6(-10.5,-5.5) AB7(-9.5,-5.5) AB8(-8.5,-5.5) AB9(-7.5,-5.5) AB10(-6.5,-5.5) AB11(-5.5,-5.5) AB12(-4.5,-5.5) AB13(-3.5,-5.5) AB14(-2.5,-5.5) AB15(-1.5,-5.5) AB16(-0.5,-5.5) AB17(0.5,-5.5) AB18(1.5,-5.5) AB19(2.5,-5.5) AB20(3.5,-5.5) AB21(4.5,-5.5) AB22(5.5,-5.5) AB23(6.5,-5.5) AB24(7.5,-5.5) AB25(8.5,-5.5) AB26(9.5,-5.5) AB27(10.5,-5.5) AB28(11.5,-5.5) AB29(12.5,-5.5) AB30(13.5,-5.5) AB31(14.5,-5.5) AB32(15.5,-5.5) AC1(-15.5,-6.5) AC2(-14.5,-6.5) AC3(-13.5,-6.5) AC4(-12.5,-6.5) AC5(-11.5,-6.5) AC6(-10.5,-6.5) AC7(-9.5,-6.5) AC8(-8.5,-6.5) AC9(-7.5,-6.5) AC10(-6.5,-6.5) AC11(-5.5,-6.5) AC12(-4.5,-6.5) AC13(-3.5,-6.5) AC14(-2.5,-6.5) AC15(-1.5,-6.5) AC16(-0.5,-6.5) AC17(0.5,-6.5) AC18(1.5,-6.5) AC19(2.5,-6.5) AC20(3.5,-6.5) AC21(4.5,-6.5) AC22(5.5,-6.5) AC23(6.5,-6.5) AC24(7.5,-6.5) AC25(8.5,-6.5) AC26(9.5,-6.5) AC27(10.5,-6.5) AC28(11.5,-6.5) AC29(12.5,-6.5) AC30(13.5,-6.5) AC31(14.5,-6.5) AC32(15.5,-6.5) AD1(-15.5,-7.5) AD2(-14.5,-7.5) AD3(-13.5,-7.5) AD4(-12.5,-7.5) AD5(-11.5,-7.5) AD6(-10.5,-7.5) AD7(-9.5,-7.5) AD8(-8.5,-7.5) AD9(-7.5,-7.5) AD10(-6.5,-7.5) AD11(-5.5,-7.5) AD12(-4.5,-7.5) AD13(-3.5,-7.5) AD14(-2.5,-7.5) AD15(-1.5,-7.5) AD16(-0.5,-7.5) AD17(0.5,-7.5) AD18(1.5,-7.5) AD19(2.5,-7.5) AD20(3.5,-7.5) AD21(4.5,-7.5) AD22(5.5,-7.5) AD23(6.5,-7.5) AD24(7.5,-7.5) AD25(8.5,-7.5) AD26(9.5,-7.5) AD27(10.5,-7.5) AD28(11.5,-7.5) AD29(12.5,-7.5) AD30(13.5,-7.5) AD31(14.5,-7.5) AD32(15.5,-7.5) AE1(-15.5,-8.5) AE2(-14.5,-8.5) AE3(-13.5,-8.5) AE4(-12.5,-8.5) AE5(-11.5,-8.5) AE6(-10.5,-8.5) AE7(-9.5,-8.5) AE8(-8.5,-8.5) AE9(-7.5,-8.5) AE10(-6.5,-8.5) AE11(-5.5,-8.5) AE12(-4.5,-8.5) AE13(-3.5,-8.5) AE14(-2.5,-8.5) AE15(-1.5,-8.5) AE16(-0.5,-8.5) AE17(0.5,-8.5) AE18(1.5,-8.5) AE19(2.5,-8.5) AE20(3.5,-8.5) AE21(4.5,-8.5) AE22(5.5,-8.5) AE23(6.5,-8.5) AE24(7.5,-8.5) AE25(8.5,-8.5) AE26(9.5,-8.5) AE27(10.5,-8.5) AE28(11.5,-8.5) AE29(12.5,-8.5) AE30(13.5,-8.5) AE31(14.5,-8.5) AE32(15.5,-8.5) AF1(-15.5,-9.5) AF2(-14.5,-9.5) AF3(-13.5,-9.5) AF4(-12.5,-9.5) AF5(-11.5,-9.5) AF6(-10.5,-9.5) AF7(-9.5,-9.5) AF8(-8.5,-9.5) AF9(-7.5,-9.5) AF10(-6.5,-9.5) AF11(-5.5,-9.5) AF12(-4.5,-9.5) AF13(-3.5,-9.5) AF14(-2.5,-9.5) AF15(-1.5,-9.5) AF16(-0.5,-9.5) AF17(0.5,-9.5) AF18(1.5,-9.5) AF19(2.5,-9.5) AF20(3.5,-9.5) AF21(4.5,-9.5) AF22(5.5,-9.5) AF23(6.5,-9.5) AF24(7.5,-9.5) AF25(8.5,-9.5) AF26(9.5,-9.5) AF27(10.5,-9.5) AF28(11.5,-9.5) AF29(12.5,-9.5) AF30(13.5,-9.5) AF31(14.5,-9.5) AF32(15.5,-9.5) AG1(-15.5,-10.5) AG2(-14.5,-10.5) AG3(-13.5,-10.5) AG4(-12.5,-10.5) AG5(-11.5,-10.5) AG6(-10.5,-10.5) AG7(-9.5,-10.5) AG8(-8.5,-10.5) AG9(-7.5,-10.5) AG10(-6.5,-10.5) AG11(-5.5,-10.5) AG12(-4.5,-10.5) AG13(-3.5,-10.5) AG14(-2.5,-10.5) AG15(-1.5,-10.5) AG16(-0.5,-10.5) AG17(0.5,-10.5) AG18(1.5,-10.5) AG19(2.5,-10.5) AG20(3.5,-10.5) AG21(4.5,-10.5) AG22(5.5,-10.5) AG23(6.5,-10.5) AG24(7.5,-10.5) AG25(8.5,-10.5) AG26(9.5,-10.5) AG27(10.5,-10.5) AG28(11.5,-10.5) AG29(12.5,-10.5) AG30(13.5,-10.5) AG31(14.5,-10.5) AG32(15.5,-10.5) AH1(-15.5,-11.5) AH2(-14.5,-11.5) AH3(-13.5,-11.5) AH4(-12.5,-11.5) AH5(-11.5,-11.5) AH6(-10.5,-11.5) AH7(-9.5,-11.5) AH8(-8.5,-11.5) AH9(-7.5,-11.5) AH10(-6.5,-11.5) AH11(-5.5,-11.5) AH12(-4.5,-11.5) AH13(-3.5,-11.5) AH14(-2.5,-11.5) AH15(-1.5,-11.5) AH16(-0.5,-11.5) AH17(0.5,-11.5) AH18(1.5,-11.5) AH19(2.5,-11.5) AH20(3.5,-11.5) AH21(4.5,-11.5) AH22(5.5,-11.5) AH23(6.5,-11.5) AH24(7.5,-11.5) AH25(8.5,-11.5) AH26(9.5,-11.5) AH27(10.5,-11.5) AH28(11.5,-11.5) AH29(12.5,-11.5) AH30(13.5,-11.5) AH31(14.5,-11.5) AH32(15.5,-11.5) AJ1(-15.5,-12.5) AJ2(-14.5,-12.5) AJ3(-13.5,-12.5) AJ4(-12.5,-12.5) AJ5(-11.5,-12.5) AJ6(-10.5,-12.5) AJ7(-9.5,-12.5) AJ8(-8.5,-12.5) AJ9(-7.5,-12.5) AJ10(-6.5,-12.5) AJ11(-5.5,-12.5) AJ12(-4.5,-12.5) AJ13(-3.5,-12.5) AJ14(-2.5,-12.5) AJ15(-1.5,-12.5) AJ16(-0.5,-12.5) AJ17(0.5,-12.5) AJ18(1.5,-12.5) AJ19(2.5,-12.5) AJ20(3.5,-12.5) AJ21(4.5,-12.5) AJ22(5.5,-12.5) AJ23(6.5,-12.5) AJ24(7.5,-12.5) AJ25(8.5,-12.5) AJ26(9.5,-12.5) AJ27(10.5,-12.5) AJ28(11.5,-12.5) AJ29(12.5,-12.5) AJ30(13.5,-12.5) AJ31(14.5,-12.5) AJ32(15.5,-12.5) AK1(-15.5,-13.5) AK2(-14.5,-13.5) AK3(-13.5,-13.5) AK4(-12.5,-13.5) AK5(-11.5,-13.5) AK6(-10.5,-13.5) AK7(-9.5,-13.5) AK8(-8.5,-13.5) AK9(-7.5,-13.5) AK10(-6.5,-13.5) AK11(-5.5,-13.5) AK12(-4.5,-13.5) AK13(-3.5,-13.5) AK14(-2.5,-13.5) AK15(-1.5,-13.5) AK16(-0.5,-13.5) AK17(0.5,-13.5) AK18(1.5,-13.5) AK19(2.5,-13.5) AK20(3.5,-13.5) AK21(4.5,-13.5) AK22(5.5,-13.5) AK23(6.5,-13.5) AK24(7.5,-13.5) AK25(8.5,-13.5) AK26(9.5,-13.5) AK27(10.5,-13.5) AK28(11.5,-13.5) AK29(12.5,-13.5) AK30(13.5,-13.5) AK31(14.5,-13.5) AK32(15.5,-13.5) AL1(-15.5,-14.5) AL2(-14.5,-14.5) AL3(-13.5,-14.5) AL4(-12.5,-14.5) AL5(-11.5,-14.5) AL6(-10.5,-14.5) AL7(-9.5,-14.5) AL8(-8.5,-14.5) AL9(-7.5,-14.5) AL10(-6.5,-14.5) AL11(-5.5,-14.5) AL12(-4.5,-14.5) AL13(-3.5,-14.5) AL14(-2.5,-14.5) AL15(-1.5,-14.5) AL16(-0.5,-14.5) AL17(0.5,-14.5) AL18(1.5,-14.5) AL19(2.5,-14.5) AL20(3.5,-14.5) AL21(4.5,-14.5) AL22(5.5,-14.5) AL23(6.5,-14.5) AL24(7.5,-14.5) AL25(8.5,-14.5) AL26(9.5,-14.5) AL27(10.5,-14.5) AL28(11.5,-14.5) AL29(12.5,-14.5) AL30(13.5,-14.5) AL31(14.5,-14.5) AL32(15.5,-14.5) AM2(-14.5,-15.5) AM3(-13.5,-15.5) AM4(-12.5,-15.5) AM5(-11.5,-15.5) AM6(-10.5,-15.5) AM7(-9.5,-15.5) AM8(-8.5,-15.5) AM9(-7.5,-15.5) AM10(-6.5,-15.5) AM11(-5.5,-15.5) AM12(-4.5,-15.5) AM13(-3.5,-15.5) AM14(-2.5,-15.5) AM15(-1.5,-15.5) AM16(-0.5,-15.5) AM17(0.5,-15.5) AM18(1.5,-15.5) AM19(2.5,-15.5) AM20(3.5,-15.5) AM21(4.5,-15.5) AM22(5.5,-15.5) AM23(6.5,-15.5) AM24(7.5,-15.5) AM25(8.5,-15.5) AM26(9.5,-15.5) AM27(10.5,-15.5) AM28(11.5,-15.5) AM29(12.5,-15.5) AM30(13.5,-15.5) AM31(14.5,-15.5) B1(-15.5,14.5) B2(-14.5,14.5) B3(-13.5,14.5) B4(-12.5,14.5) B5(-11.5,14.5) B6(-10.5,14.5) B7(-9.5,14.5) B8(-8.5,14.5) B9(-7.5,14.5) B10(-6.5,14.5) B11(-5.5,14.5) B12(-4.5,14.5) B13(-3.5,14.5) B14(-2.5,14.5) B15(-1.5,14.5) B16(-0.5,14.5) B17(0.5,14.5) B18(1.5,14.5) B19(2.5,14.5) B20(3.5,14.5) B21(4.5,14.5) B22(5.5,14.5) B23(6.5,14.5) B24(7.5,14.5) B25(8.5,14.5) B26(9.5,14.5) B27(10.5,14.5) B28(11.5,14.5) B29(12.5,14.5) B30(13.5,14.5) B31(14.5,14.5) B32(15.5,14.5) C1(-15.5,13.5) C2(-14.5,13.5) C3(-13.5,13.5) C4(-12.5,13.5) C5(-11.5,13.5) C6(-10.5,13.5) C7(-9.5,13.5) C8(-8.5,13.5) C9(-7.5,13.5) C10(-6.5,13.5) C11(-5.5,13.5) C12(-4.5,13.5) C13(-3.5,13.5) C14(-2.5,13.5) C15(-1.5,13.5) C16(-0.5,13.5) C17(0.5,13.5) C18(1.5,13.5) C19(2.5,13.5) C20(3.5,13.5) C21(4.5,13.5) C22(5.5,13.5) C23(6.5,13.5) C24(7.5,13.5) C25(8.5,13.5) C26(9.5,13.5) C27(10.5,13.5) C28(11.5,13.5) C29(12.5,13.5) C30(13.5,13.5) C31(14.5,13.5) C32(15.5,13.5) D1(-15.5,12.5) D2(-14.5,12.5) D3(-13.5,12.5) D4(-12.5,12.5) D5(-11.5,12.5) D6(-10.5,12.5) D7(-9.5,12.5) D8(-8.5,12.5) D9(-7.5,12.5) D10(-6.5,12.5) D11(-5.5,12.5) D12(-4.5,12.5) D13(-3.5,12.5) D14(-2.5,12.5) D15(-1.5,12.5) D16(-0.5,12.5) D17(0.5,12.5) D18(1.5,12.5) D19(2.5,12.5) D20(3.5,12.5) D21(4.5,12.5) D22(5.5,12.5) D23(6.5,12.5) D24(7.5,12.5) D25(8.5,12.5) D26(9.5,12.5) D27(10.5,12.5) D28(11.5,12.5) D29(12.5,12.5) D30(13.5,12.5) D31(14.5,12.5) D32(15.5,12.5) E1(-15.5,11.5) E2(-14.5,11.5) E3(-13.5,11.5) E4(-12.5,11.5) E5(-11.5,11.5) E6(-10.5,11.5) E7(-9.5,11.5) E8(-8.5,11.5) E9(-7.5,11.5) E10(-6.5,11.5) E11(-5.5,11.5) E12(-4.5,11.5) E13(-3.5,11.5) E14(-2.5,11.5) E15(-1.5,11.5) E16(-0.5,11.5) E17(0.5,11.5) E18(1.5,11.5) E19(2.5,11.5) E20(3.5,11.5) E21(4.5,11.5) E22(5.5,11.5) E23(6.5,11.5) E24(7.5,11.5) E25(8.5,11.5) E26(9.5,11.5) E27(10.5,11.5) E28(11.5,11.5) E29(12.5,11.5) E30(13.5,11.5) E31(14.5,11.5) E32(15.5,11.5) F1(-15.5,10.5) F2(-14.5,10.5) F3(-13.5,10.5) F4(-12.5,10.5) F5(-11.5,10.5) F6(-10.5,10.5) F7(-9.5,10.5) F8(-8.5,10.5) F9(-7.5,10.5) F10(-6.5,10.5) F11(-5.5,10.5) F12(-4.5,10.5) F13(-3.5,10.5) F14(-2.5,10.5) F15(-1.5,10.5) F16(-0.5,10.5) F17(0.5,10.5) F18(1.5,10.5) F19(2.5,10.5) F20(3.5,10.5) F21(4.5,10.5) F22(5.5,10.5) F23(6.5,10.5) F24(7.5,10.5) F25(8.5,10.5) F26(9.5,10.5) F27(10.5,10.5) F28(11.5,10.5) F29(12.5,10.5) F30(13.5,10.5) F31(14.5,10.5) F32(15.5,10.5) G1(-15.5,9.5) G2(-14.5,9.5) G3(-13.5,9.5) G4(-12.5,9.5) G5(-11.5,9.5) G6(-10.5,9.5) G7(-9.5,9.5) G8(-8.5,9.5) G9(-7.5,9.5) G10(-6.5,9.5) G11(-5.5,9.5) G12(-4.5,9.5) G13(-3.5,9.5) G14(-2.5,9.5) G15(-1.5,9.5) G16(-0.5,9.5) G17(0.5,9.5) G18(1.5,9.5) G19(2.5,9.5) G20(3.5,9.5) G21(4.5,9.5) G22(5.5,9.5) G23(6.5,9.5) G24(7.5,9.5) G25(8.5,9.5) G26(9.5,9.5) G27(10.5,9.5) G28(11.5,9.5) G29(12.5,9.5) G30(13.5,9.5) G31(14.5,9.5) G32(15.5,9.5) H1(-15.5,8.5) H2(-14.5,8.5) H3(-13.5,8.5) H4(-12.5,8.5) H5(-11.5,8.5) H6(-10.5,8.5) H7(-9.5,8.5) H8(-8.5,8.5) H9(-7.5,8.5) H10(-6.5,8.5) H11(-5.5,8.5) H12(-4.5,8.5) H13(-3.5,8.5) H14(-2.5,8.5) H15(-1.5,8.5) H16(-0.5,8.5) H17(0.5,8.5) H18(1.5,8.5) H19(2.5,8.5) H20(3.5,8.5) H21(4.5,8.5) H22(5.5,8.5) H23(6.5,8.5) H24(7.5,8.5) H25(8.5,8.5) H26(9.5,8.5) H27(10.5,8.5) H28(11.5,8.5) H29(12.5,8.5) H30(13.5,8.5) H31(14.5,8.5) H32(15.5,8.5) J1(-15.5,7.5) J2(-14.5,7.5) J3(-13.5,7.5) J4(-12.5,7.5) J5(-11.5,7.5) J6(-10.5,7.5) J7(-9.5,7.5) J8(-8.5,7.5) J9(-7.5,7.5) J10(-6.5,7.5) J11(-5.5,7.5) J12(-4.5,7.5) J13(-3.5,7.5) J14(-2.5,7.5) J15(-1.5,7.5) J16(-0.5,7.5) J17(0.5,7.5) J18(1.5,7.5) J19(2.5,7.5) J20(3.5,7.5) J21(4.5,7.5) J22(5.5,7.5) J23(6.5,7.5) J24(7.5,7.5) J25(8.5,7.5) J26(9.5,7.5) J27(10.5,7.5) J28(11.5,7.5) J29(12.5,7.5) J30(13.5,7.5) J31(14.5,7.5) J32(15.5,7.5) K1(-15.5,6.5) K2(-14.5,6.5) K3(-13.5,6.5) K4(-12.5,6.5) K5(-11.5,6.5) K6(-10.5,6.5) K7(-9.5,6.5) K8(-8.5,6.5) K9(-7.5,6.5) K10(-6.5,6.5) K11(-5.5,6.5) K12(-4.5,6.5) K13(-3.5,6.5) K14(-2.5,6.5) K15(-1.5,6.5) K16(-0.5,6.5) K17(0.5,6.5) K18(1.5,6.5) K19(2.5,6.5) K20(3.5,6.5) K21(4.5,6.5) K22(5.5,6.5) K23(6.5,6.5) K24(7.5,6.5) K25(8.5,6.5) K26(9.5,6.5) K27(10.5,6.5) K28(11.5,6.5) K29(12.5,6.5) K30(13.5,6.5) K31(14.5,6.5) K32(15.5,6.5) L1(-15.5,5.5) L2(-14.5,5.5) L3(-13.5,5.5) L4(-12.5,5.5) L5(-11.5,5.5) L6(-10.5,5.5) L7(-9.5,5.5) L8(-8.5,5.5) L9(-7.5,5.5) L10(-6.5,5.5) L11(-5.5,5.5) L12(-4.5,5.5) L13(-3.5,5.5) L14(-2.5,5.5) L15(-1.5,5.5) L16(-0.5,5.5) L17(0.5,5.5) L18(1.5,5.5) L19(2.5,5.5) L20(3.5,5.5) L21(4.5,5.5) L22(5.5,5.5) L23(6.5,5.5) L24(7.5,5.5) L25(8.5,5.5) L26(9.5,5.5) L27(10.5,5.5) L28(11.5,5.5) L29(12.5,5.5) L30(13.5,5.5) L31(14.5,5.5) L32(15.5,5.5) M1(-15.5,4.5) M2(-14.5,4.5) M3(-13.5,4.5) M4(-12.5,4.5) M5(-11.5,4.5) M6(-10.5,4.5) M7(-9.5,4.5) M8(-8.5,4.5) M9(-7.5,4.5) M10(-6.5,4.5) M11(-5.5,4.5) M12(-4.5,4.5) M13(-3.5,4.5) M14(-2.5,4.5) M15(-1.5,4.5) M16(-0.5,4.5) M17(0.5,4.5) M18(1.5,4.5) M19(2.5,4.5) M20(3.5,4.5) M21(4.5,4.5) M22(5.5,4.5) M23(6.5,4.5) M24(7.5,4.5) M25(8.5,4.5) M26(9.5,4.5) M27(10.5,4.5) M28(11.5,4.5) M29(12.5,4.5) M30(13.5,4.5) M31(14.5,4.5) M32(15.5,4.5) N1(-15.5,3.5) N2(-14.5,3.5) N3(-13.5,3.5) N4(-12.5,3.5) N5(-11.5,3.5) N6(-10.5,3.5) N7(-9.5,3.5) N8(-8.5,3.5) N9(-7.5,3.5) N10(-6.5,3.5) N11(-5.5,3.5) N12(-4.5,3.5) N13(-3.5,3.5) N14(-2.5,3.5) N15(-1.5,3.5) N16(-0.5,3.5) N17(0.5,3.5) N18(1.5,3.5) N19(2.5,3.5) N20(3.5,3.5) N21(4.5,3.5) N22(5.5,3.5) N23(6.5,3.5) N24(7.5,3.5) N25(8.5,3.5) N26(9.5,3.5) N27(10.5,3.5) N28(11.5,3.5) N29(12.5,3.5) N30(13.5,3.5) N31(14.5,3.5) N32(15.5,3.5) P1(-15.5,2.5) P2(-14.5,2.5) P3(-13.5,2.5) P4(-12.5,2.5) P5(-11.5,2.5) P6(-10.5,2.5) P7(-9.5,2.5) P8(-8.5,2.5) P9(-7.5,2.5) P10(-6.5,2.5) P11(-5.5,2.5) P12(-4.5,2.5) P13(-3.5,2.5) P14(-2.5,2.5) P15(-1.5,2.5) P16(-0.5,2.5) P17(0.5,2.5) P18(1.5,2.5) P19(2.5,2.5) P20(3.5,2.5) P21(4.5,2.5) P22(5.5,2.5) P23(6.5,2.5) P24(7.5,2.5) P25(8.5,2.5) P26(9.5,2.5) P27(10.5,2.5) P28(11.5,2.5) P29(12.5,2.5) P30(13.5,2.5) P31(14.5,2.5) P32(15.5,2.5) R1(-15.5,1.5) R2(-14.5,1.5) R3(-13.5,1.5) R4(-12.5,1.5) R5(-11.5,1.5) R6(-10.5,1.5) R7(-9.5,1.5) R8(-8.5,1.5) R9(-7.5,1.5) R10(-6.5,1.5) R11(-5.5,1.5) R12(-4.5,1.5) R13(-3.5,1.5) R14(-2.5,1.5) R15(-1.5,1.5) R16(-0.5,1.5) R17(0.5,1.5) R18(1.5,1.5) R19(2.5,1.5) R20(3.5,1.5) R21(4.5,1.5) R22(5.5,1.5) R23(6.5,1.5) R24(7.5,1.5) R25(8.5,1.5) R26(9.5,1.5) R27(10.5,1.5) R28(11.5,1.5) R29(12.5,1.5) R30(13.5,1.5) R31(14.5,1.5) R32(15.5,1.5) T1(-15.5,0.5) T2(-14.5,0.5) T3(-13.5,0.5) T4(-12.5,0.5) T5(-11.5,0.5) T6(-10.5,0.5) T7(-9.5,0.5) T8(-8.5,0.5) T9(-7.5,0.5) T10(-6.5,0.5) T11(-5.5,0.5) T12(-4.5,0.5) T13(-3.5,0.5) T14(-2.5,0.5) T15(-1.5,0.5) T16(-0.5,0.5) T17(0.5,0.5) T18(1.5,0.5) T19(2.5,0.5) T20(3.5,0.5) T21(4.5,0.5) T22(5.5,0.5) T23(6.5,0.5) T24(7.5,0.5) T25(8.5,0.5) T26(9.5,0.5) T27(10.5,0.5) T28(11.5,0.5) T29(12.5,0.5) T30(13.5,0.5) T31(14.5,0.5) T32(15.5,0.5) U1(-15.5,-0.5) U2(-14.5,-0.5) U3(-13.5,-0.5) U4(-12.5,-0.5) U5(-11.5,-0.5) U6(-10.5,-0.5) U7(-9.5,-0.5) U8(-8.5,-0.5) U9(-7.5,-0.5) U10(-6.5,-0.5) U11(-5.5,-0.5) U12(-4.5,-0.5) U13(-3.5,-0.5) U14(-2.5,-0.5) U15(-1.5,-0.5) U16(-0.5,-0.5) U17(0.5,-0.5) U18(1.5,-0.5) U19(2.5,-0.5) U20(3.5,-0.5) U21(4.5,-0.5) U22(5.5,-0.5) U23(6.5,-0.5) U24(7.5,-0.5) U25(8.5,-0.5) U26(9.5,-0.5) U27(10.5,-0.5) U28(11.5,-0.5) U29(12.5,-0.5) U30(13.5,-0.5) U31(14.5,-0.5) U32(15.5,-0.5) V1(-15.5,-1.5) V2(-14.5,-1.5) V3(-13.5,-1.5) V4(-12.5,-1.5) V5(-11.5,-1.5) V6(-10.5,-1.5) V7(-9.5,-1.5) V8(-8.5,-1.5) V9(-7.5,-1.5) V10(-6.5,-1.5) V11(-5.5,-1.5) V12(-4.5,-1.5) V13(-3.5,-1.5) V14(-2.5,-1.5) V15(-1.5,-1.5) V16(-0.5,-1.5) V17(0.5,-1.5) V18(1.5,-1.5) V19(2.5,-1.5) V20(3.5,-1.5) V21(4.5,-1.5) V22(5.5,-1.5) V23(6.5,-1.5) V24(7.5,-1.5) V25(8.5,-1.5) V26(9.5,-1.5) V27(10.5,-1.5) V28(11.5,-1.5) V29(12.5,-1.5) V30(13.5,-1.5) V31(14.5,-1.5) V32(15.5,-1.5) W1(-15.5,-2.5) W2(-14.5,-2.5) W3(-13.5,-2.5) W4(-12.5,-2.5) W5(-11.5,-2.5) W6(-10.5,-2.5) W7(-9.5,-2.5) W8(-8.5,-2.5) W9(-7.5,-2.5) W10(-6.5,-2.5) W11(-5.5,-2.5) W12(-4.5,-2.5) W13(-3.5,-2.5) W14(-2.5,-2.5) W15(-1.5,-2.5) W16(-0.5,-2.5) W17(0.5,-2.5) W18(1.5,-2.5) W19(2.5,-2.5) W20(3.5,-2.5) W21(4.5,-2.5) W22(5.5,-2.5) W23(6.5,-2.5) W24(7.5,-2.5) W25(8.5,-2.5) W26(9.5,-2.5) W27(10.5,-2.5) W28(11.5,-2.5) W29(12.5,-2.5) W30(13.5,-2.5) W31(14.5,-2.5) W32(15.5,-2.5) Y1(-15.5,-3.5) Y2(-14.5,-3.5) Y3(-13.5,-3.5) Y4(-12.5,-3.5) Y5(-11.5,-3.5) Y6(-10.5,-3.5) Y7(-9.5,-3.5) Y8(-8.5,-3.5) Y9(-7.5,-3.5) Y10(-6.5,-3.5) Y11(-5.5,-3.5) Y12(-4.5,-3.5) Y13(-3.5,-3.5) Y14(-2.5,-3.5) Y15(-1.5,-3.5) Y16(-0.5,-3.5) Y17(0.5,-3.5) Y18(1.5,-3.5) Y19(2.5,-3.5) Y20(3.5,-3.5) Y21(4.5,-3.5) Y22(5.5,-3.5) Y23(6.5,-3.5) Y24(7.5,-3.5) Y25(8.5,-3.5) Y26(9.5,-3.5) Y27(10.5,-3.5) Y28(11.5,-3.5) Y29(12.5,-3.5) Y30(13.5,-3.5) Y31(14.5,-3.5) Y32(15.5,-3.5)
